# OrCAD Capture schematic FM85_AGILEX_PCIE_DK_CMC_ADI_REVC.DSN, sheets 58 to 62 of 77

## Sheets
58 PWR - 12V to 3.3V: size B
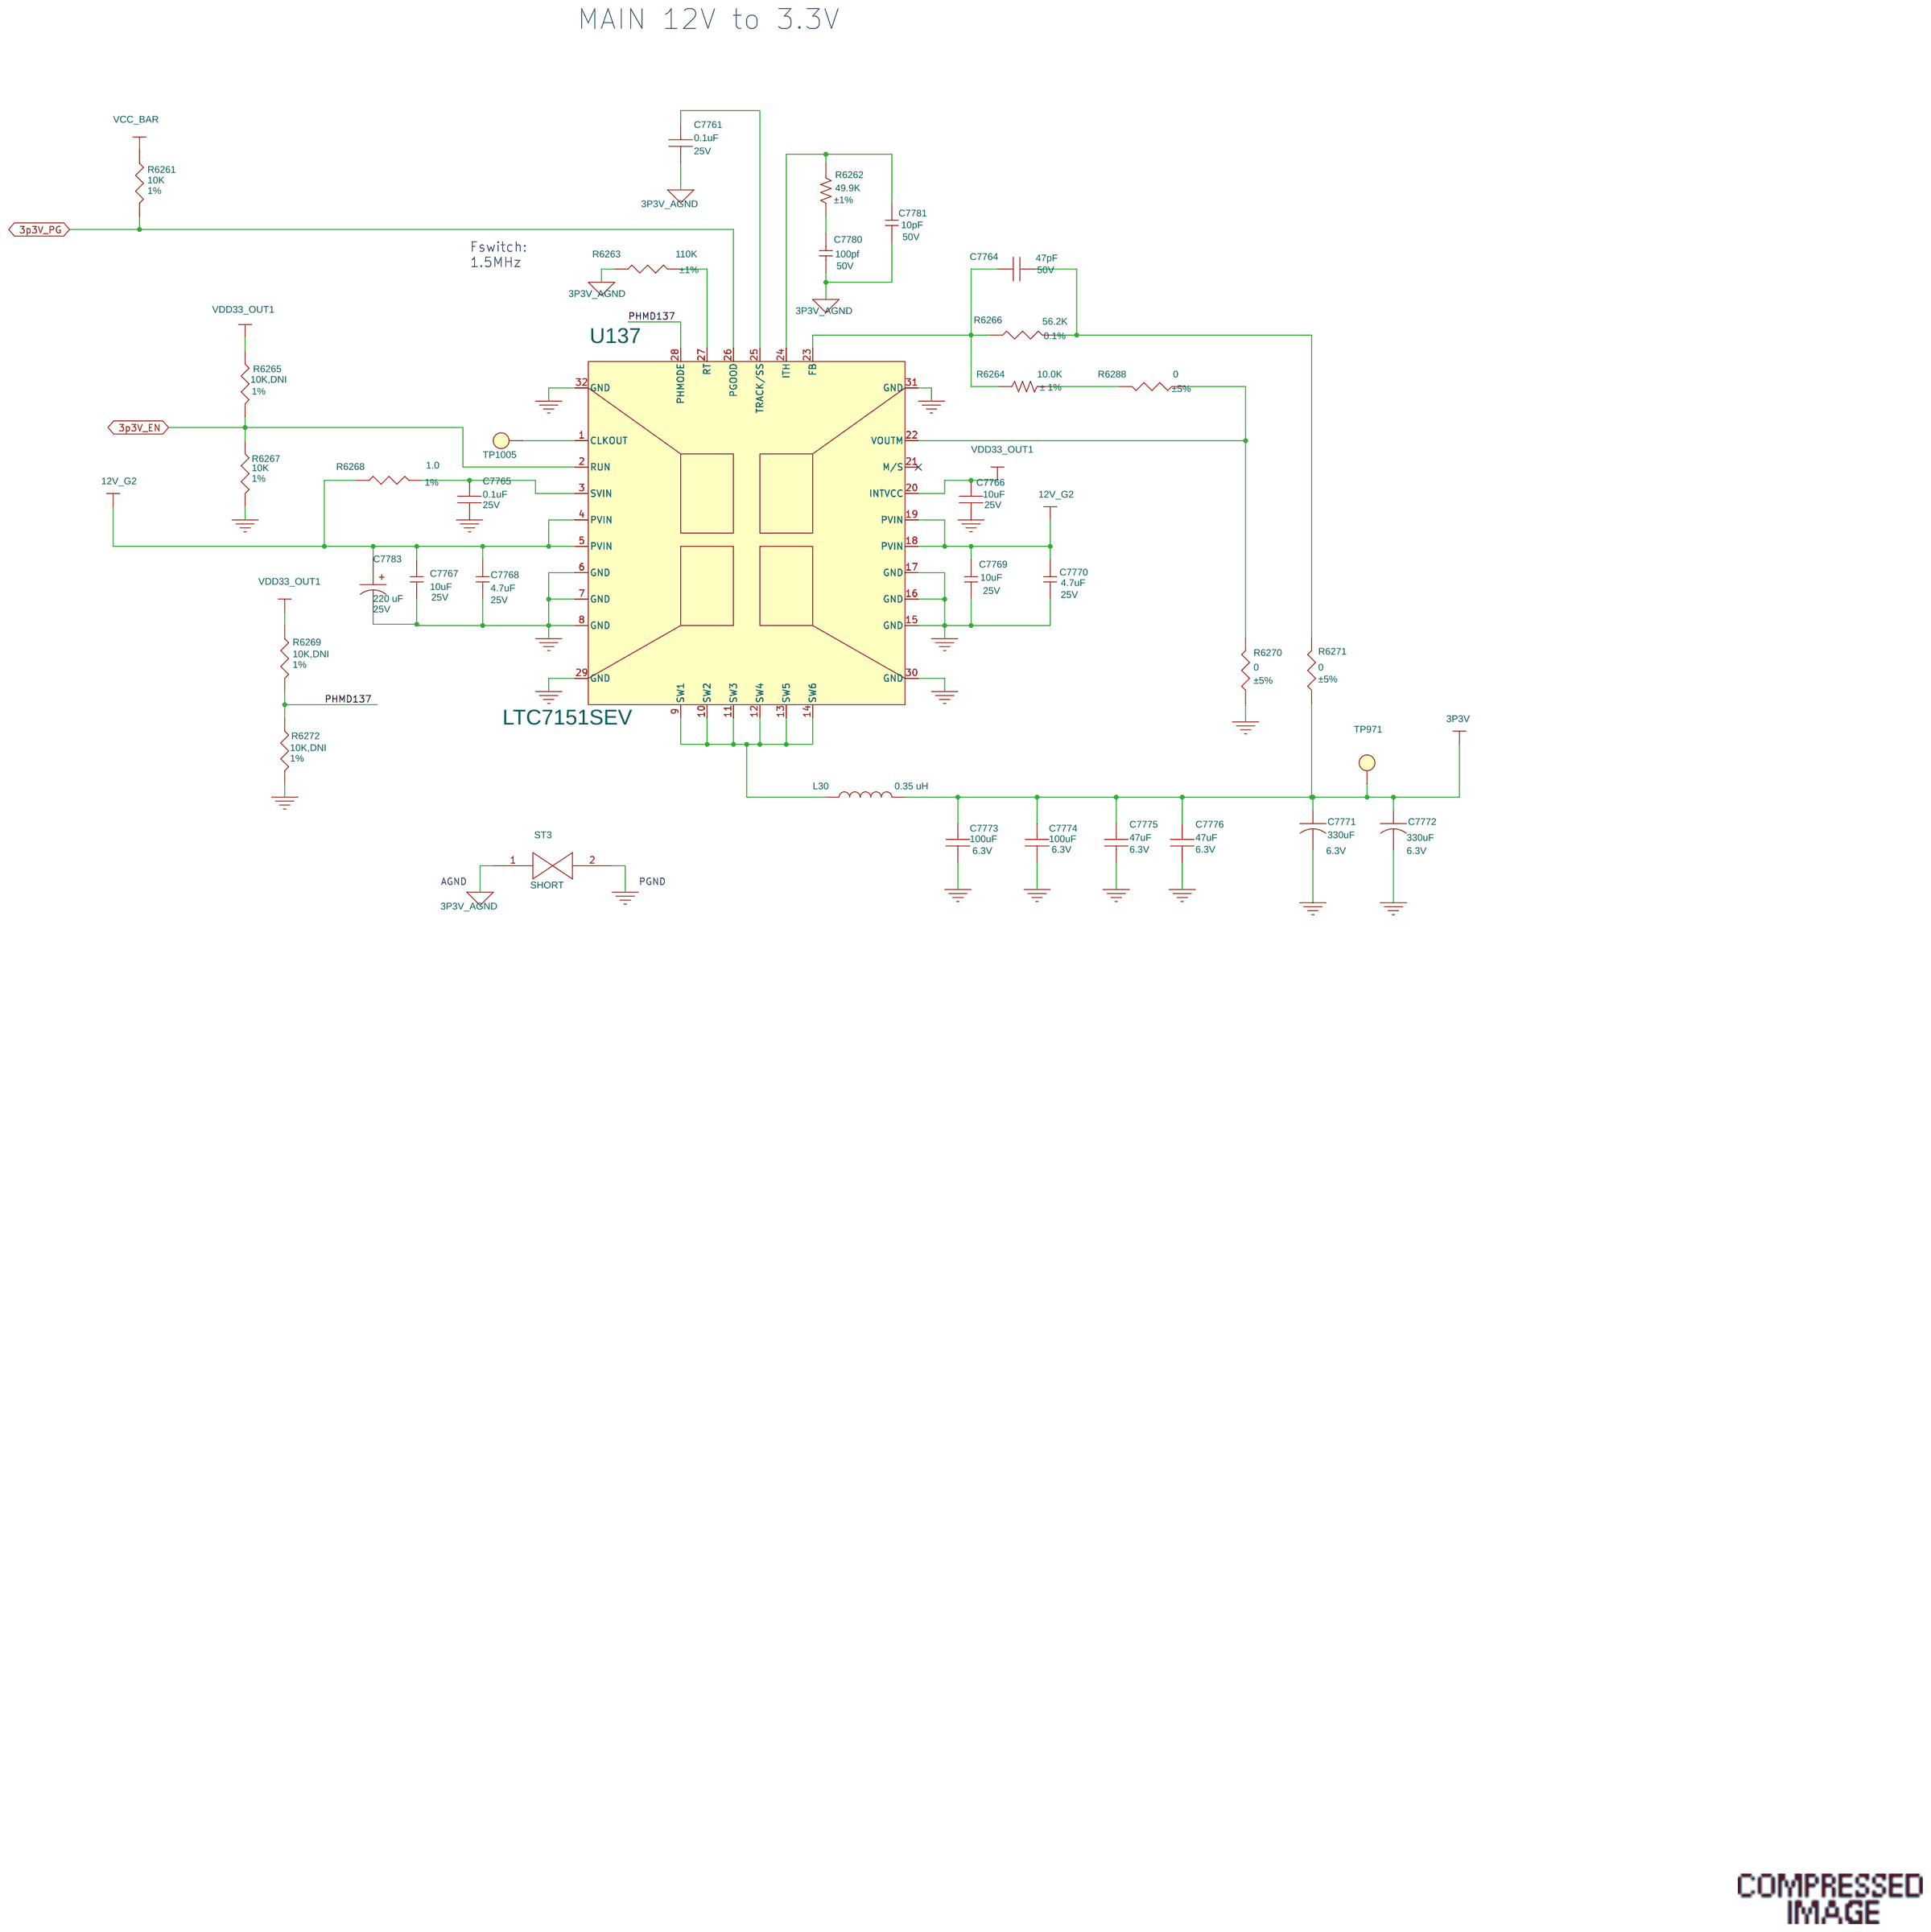
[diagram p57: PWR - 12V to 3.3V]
59 PWR - VCCR_CORE: size C
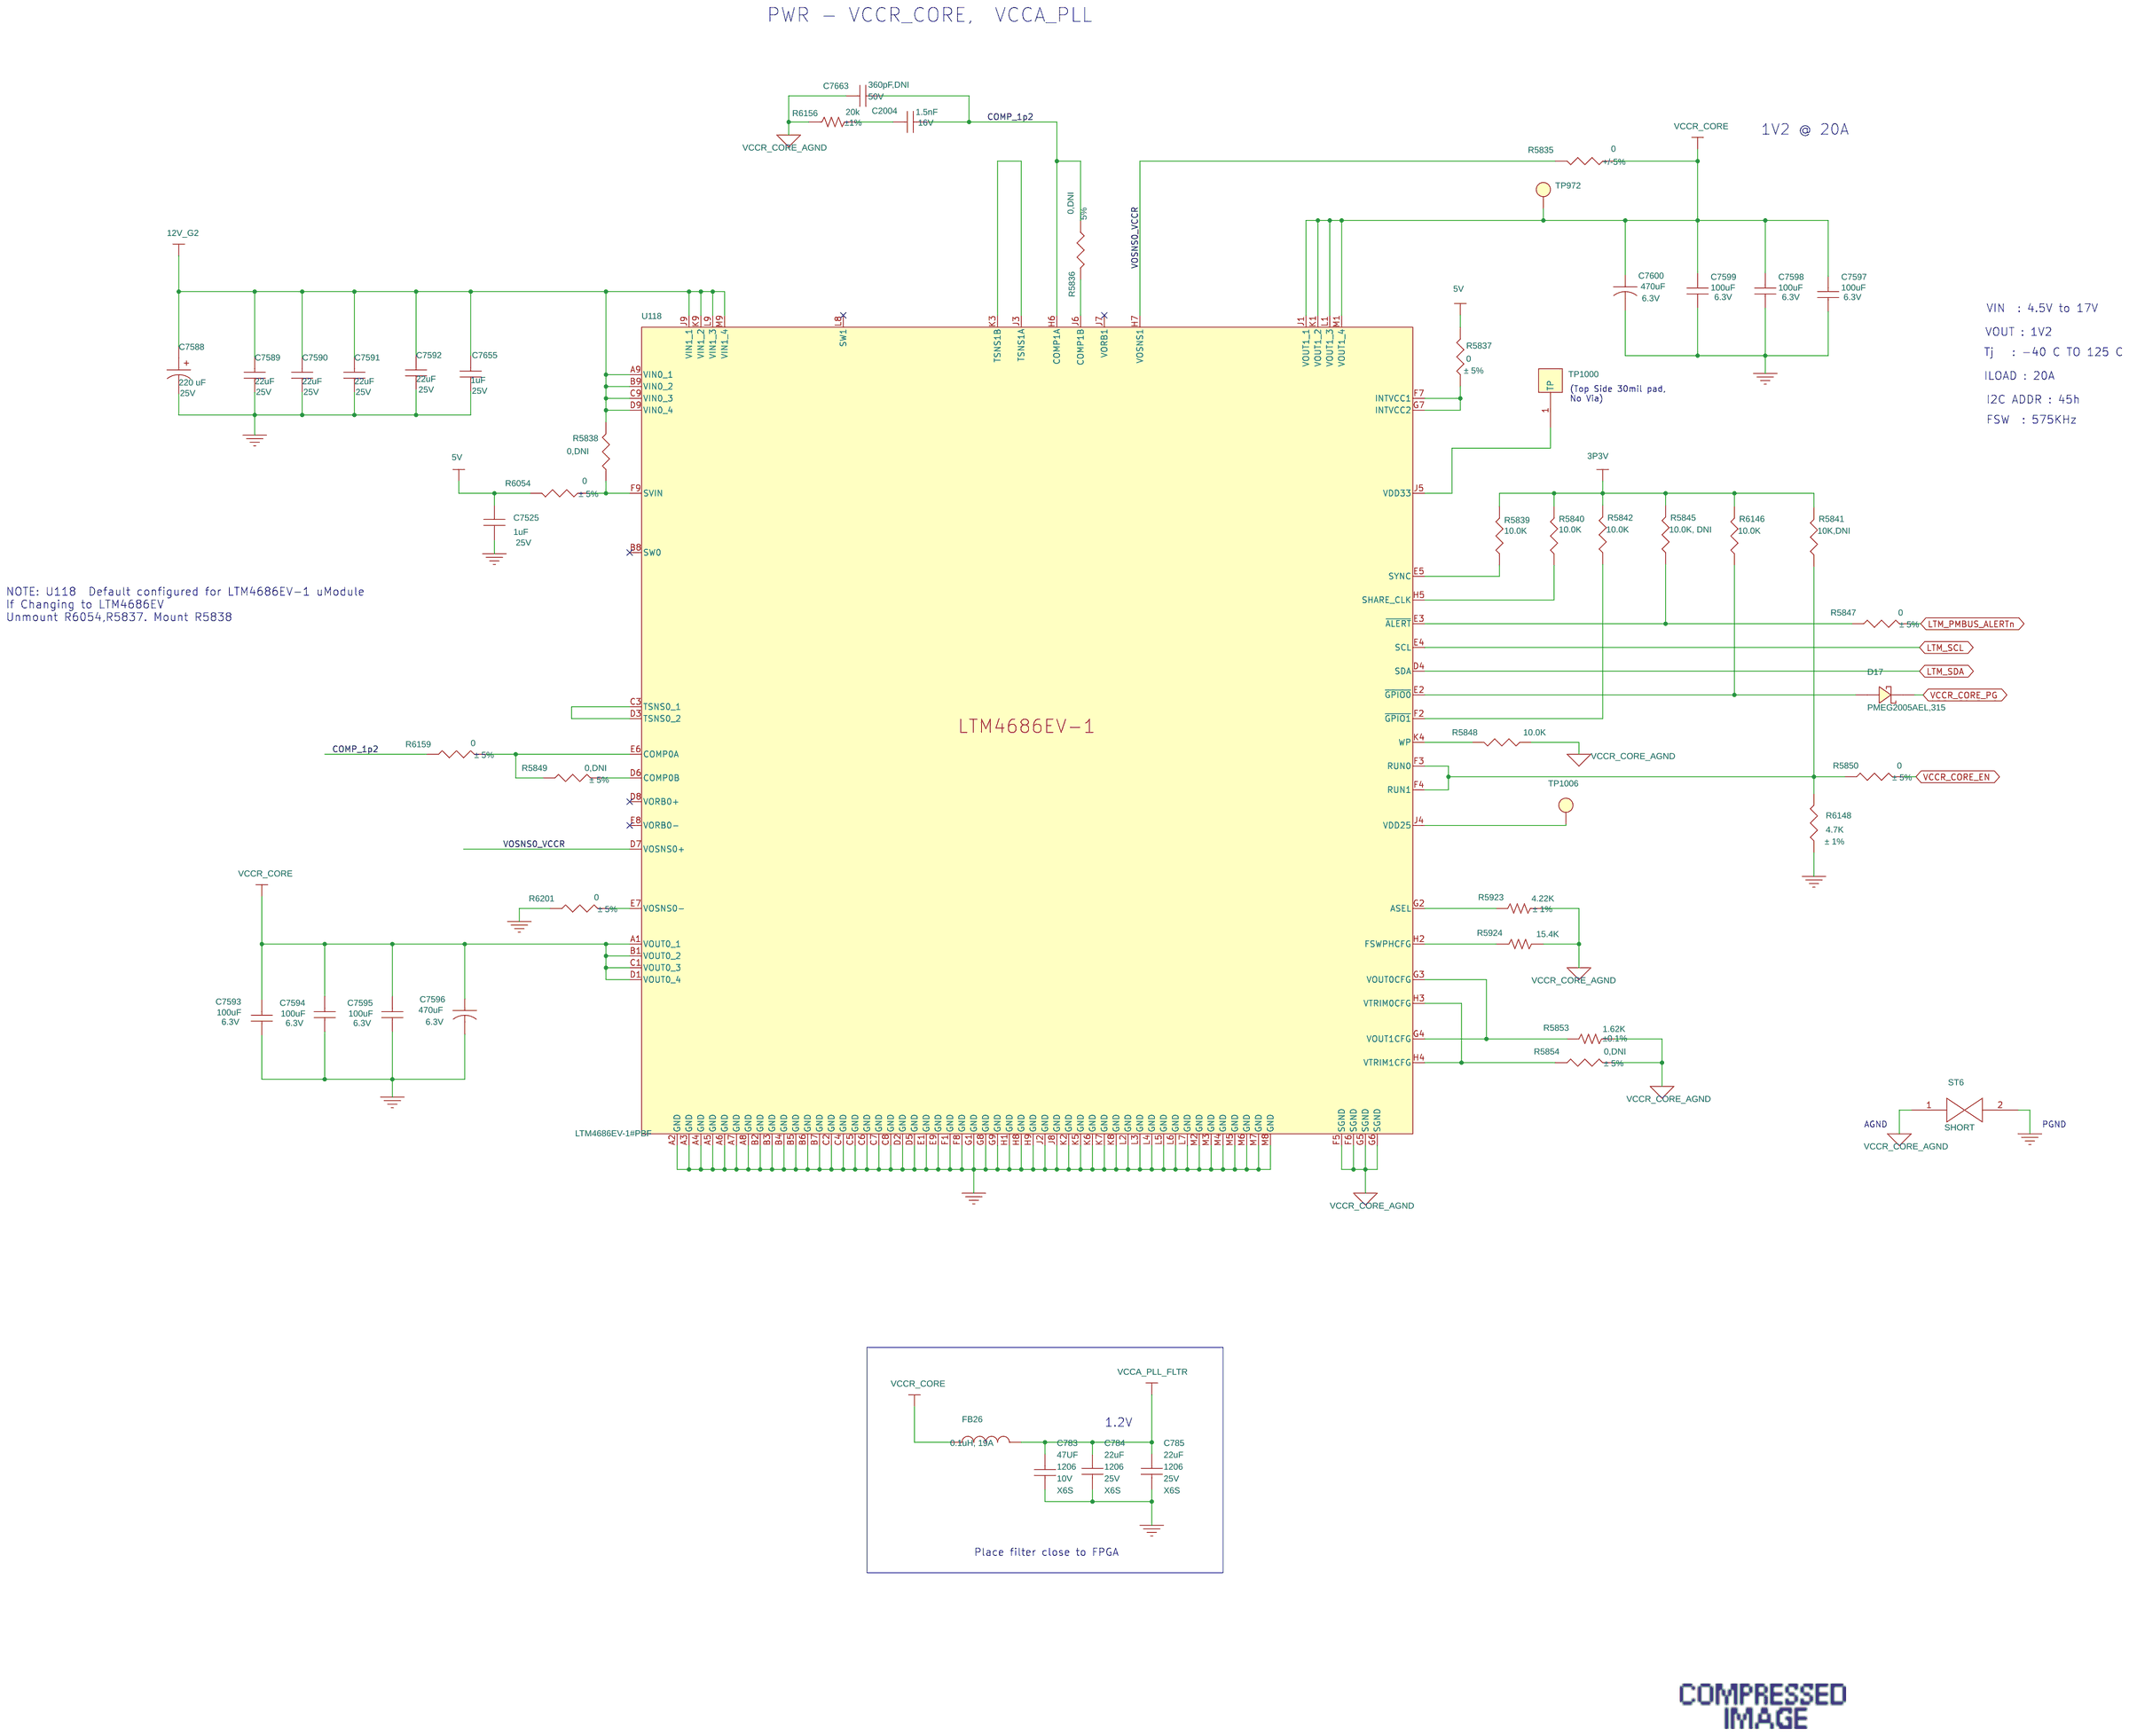
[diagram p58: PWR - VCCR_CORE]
60 PWR -VCCED_GXR: size C
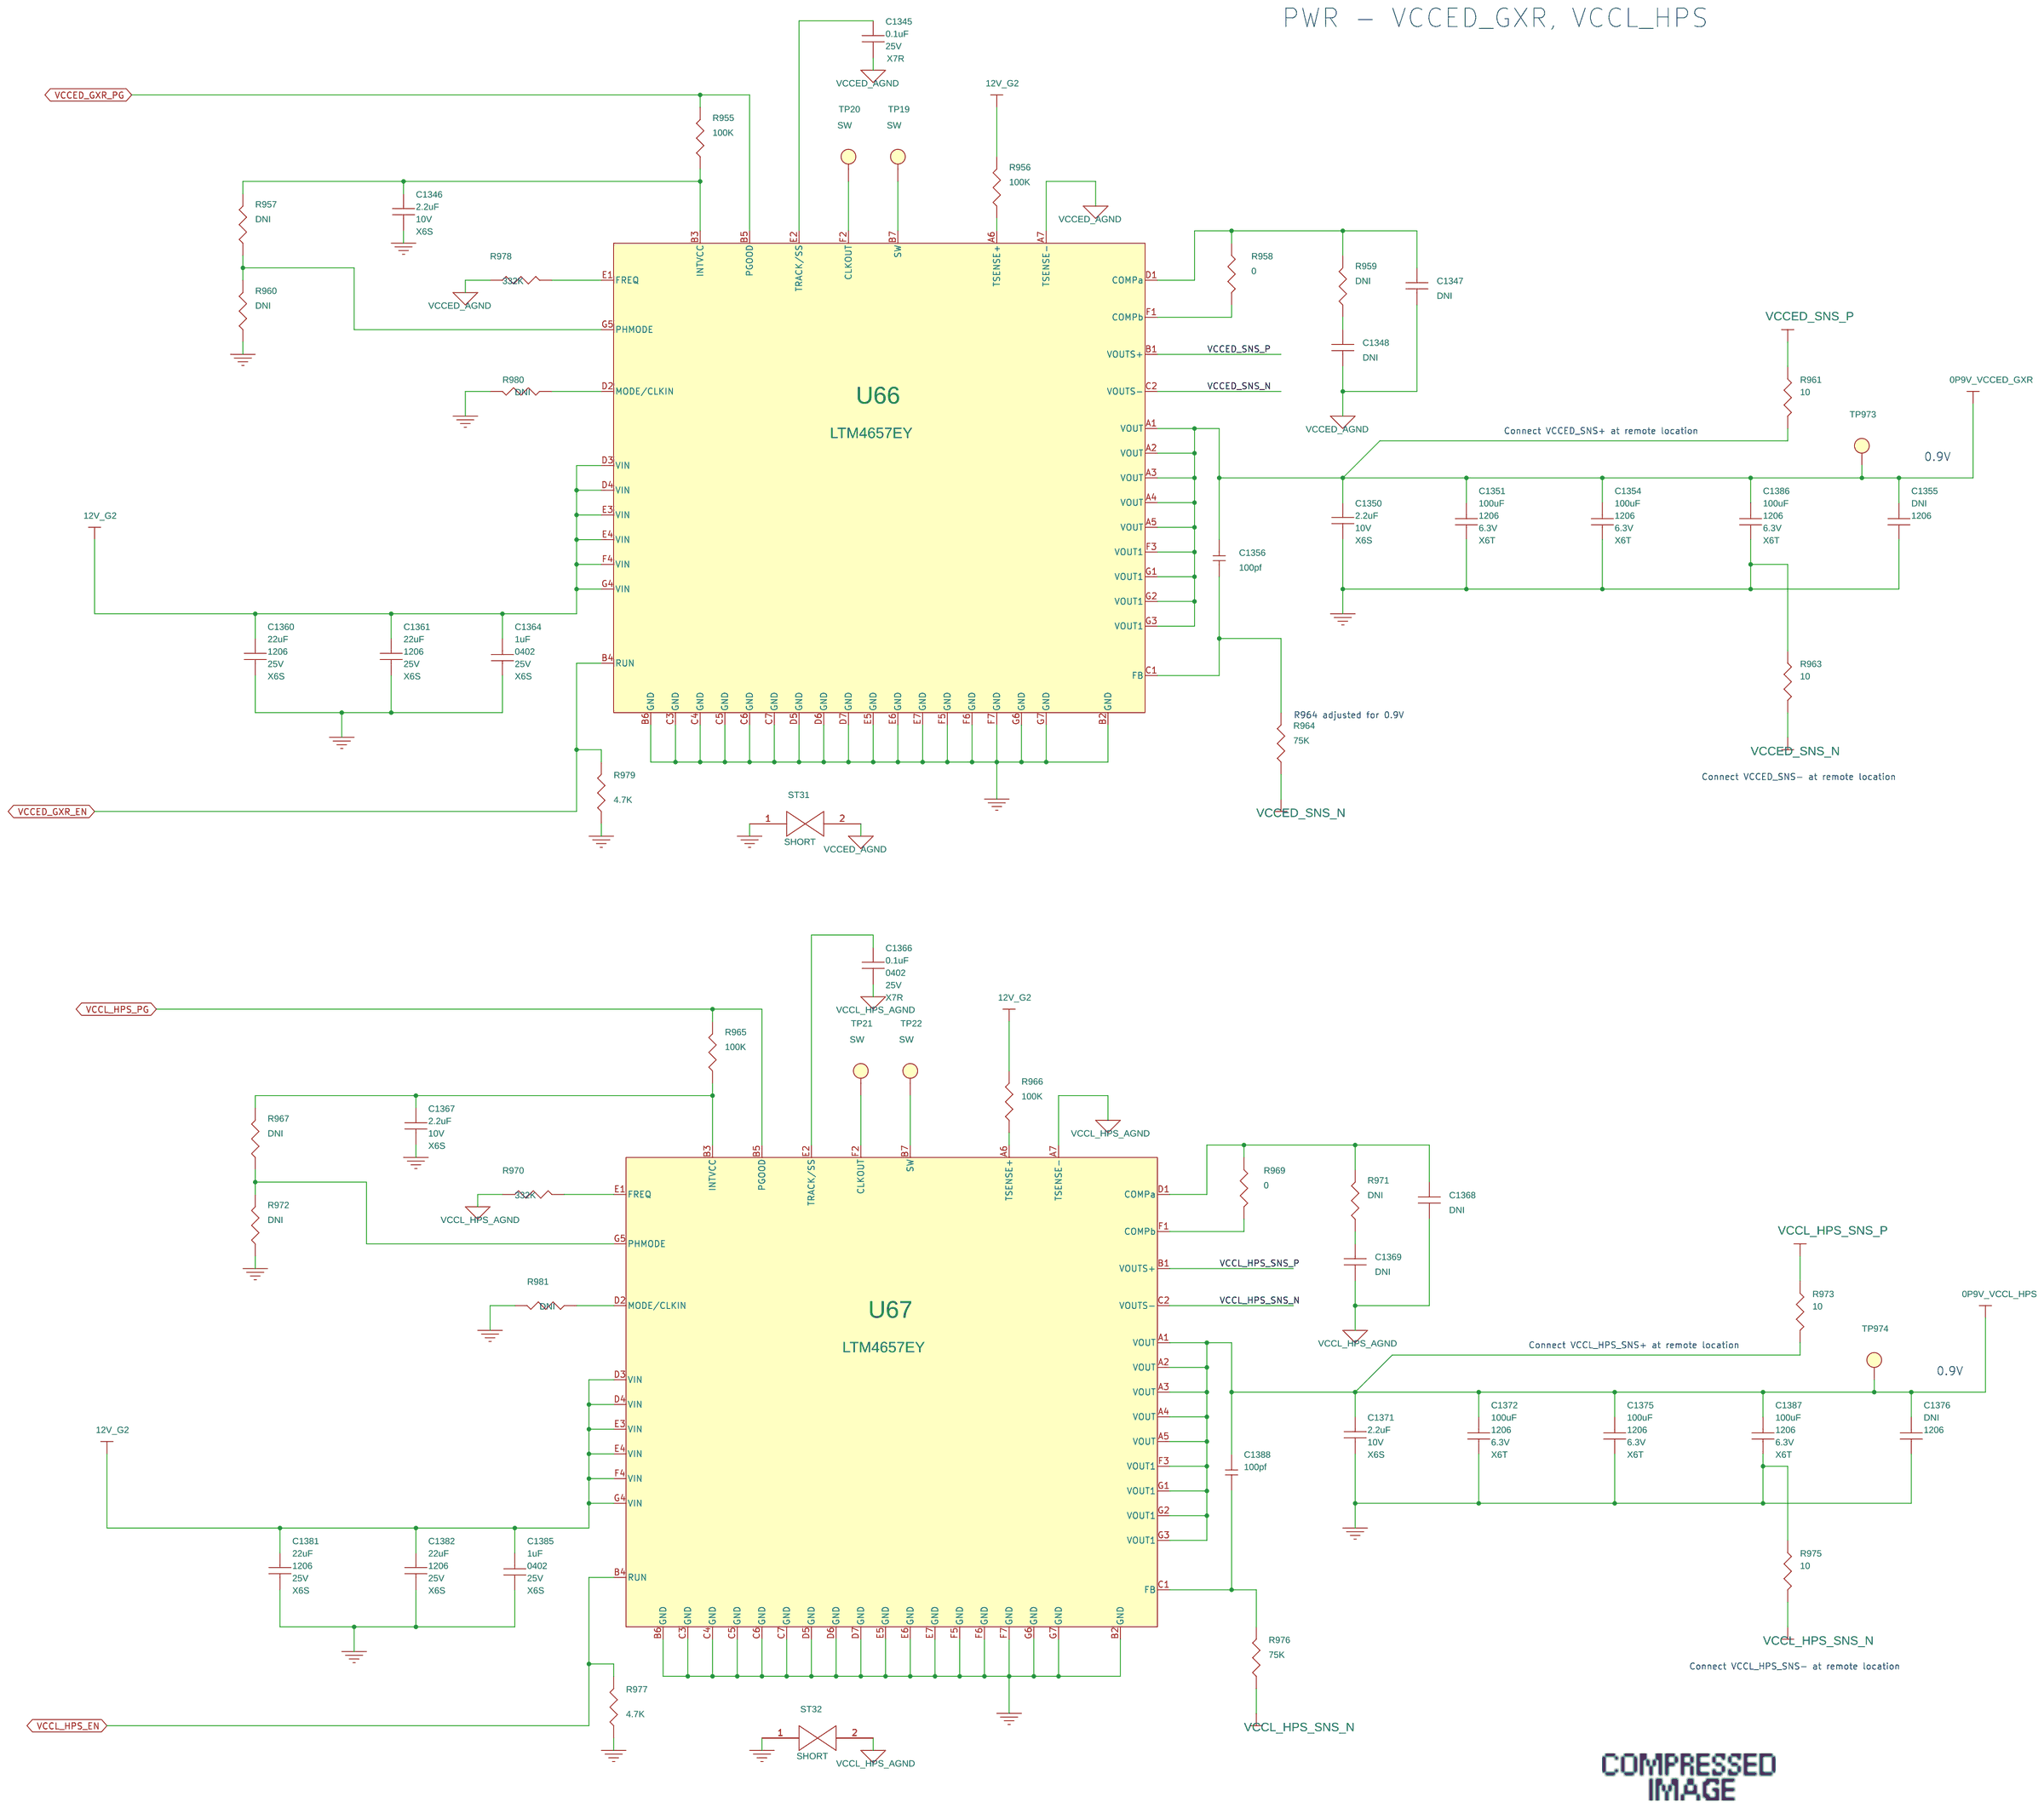
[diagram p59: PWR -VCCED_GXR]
61 PWR - VCCERT_FGT_GXF: size B
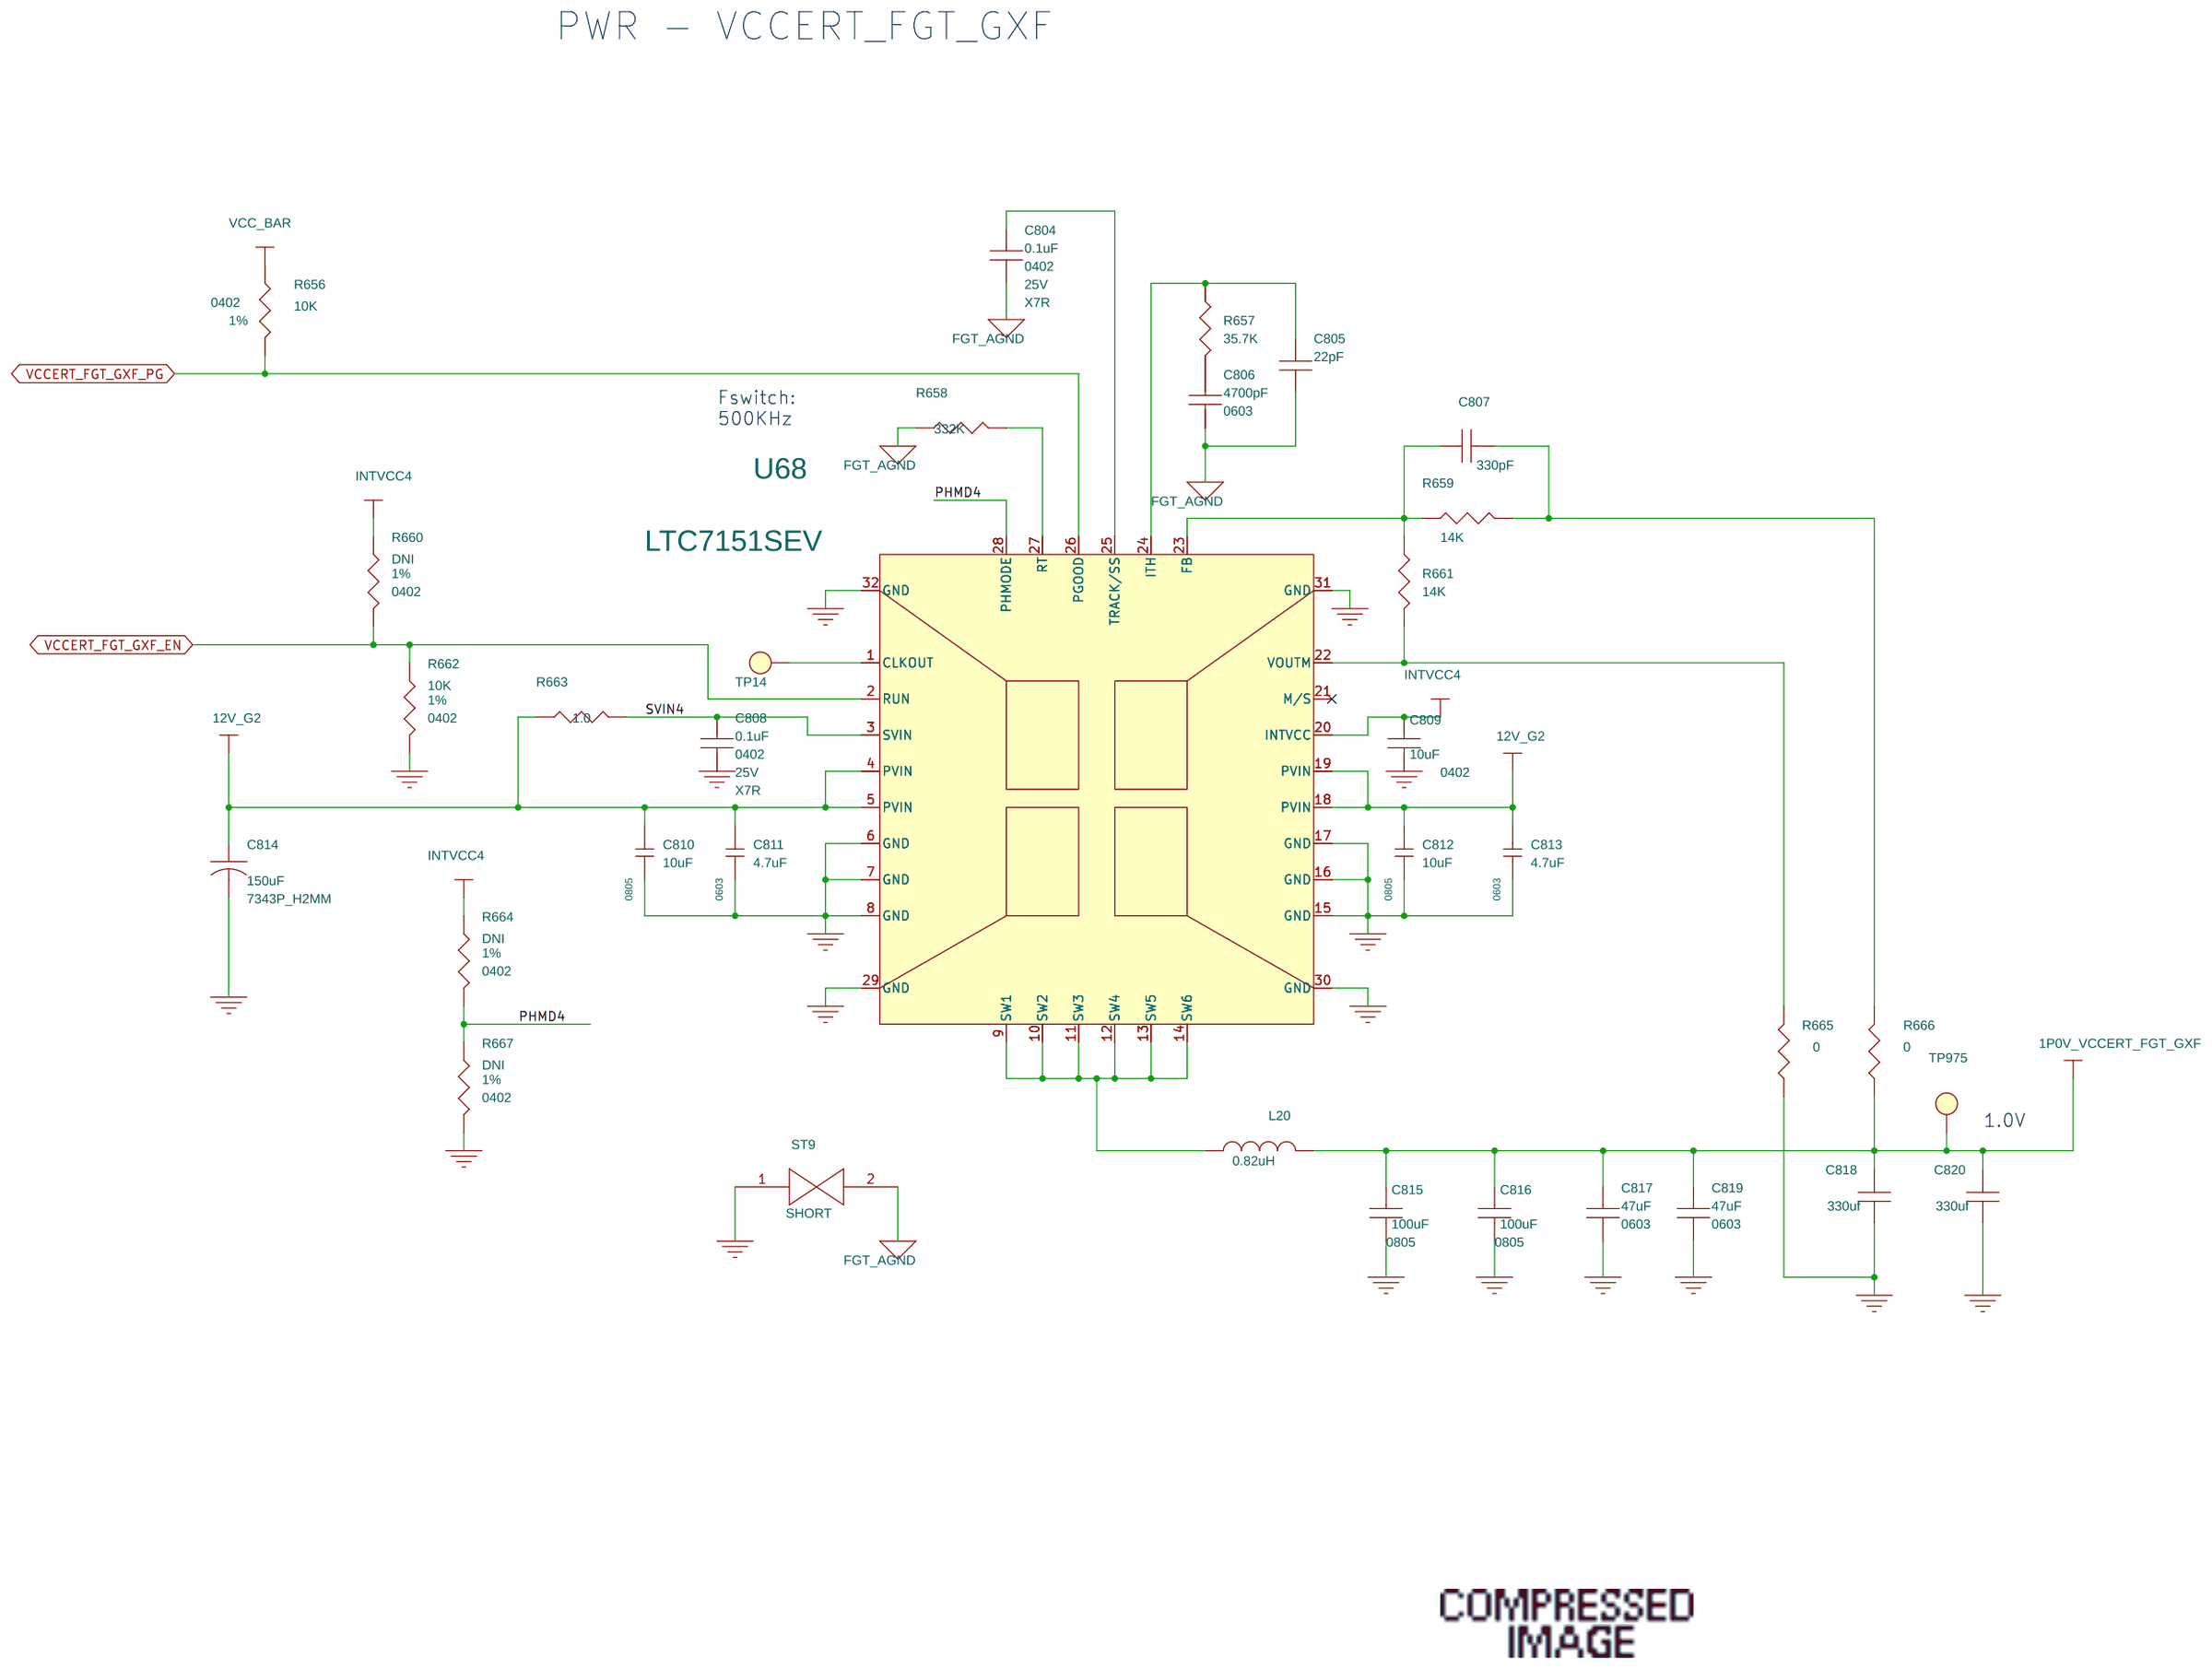
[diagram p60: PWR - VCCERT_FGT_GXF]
62 PWR -VCCRT_GXR: size B
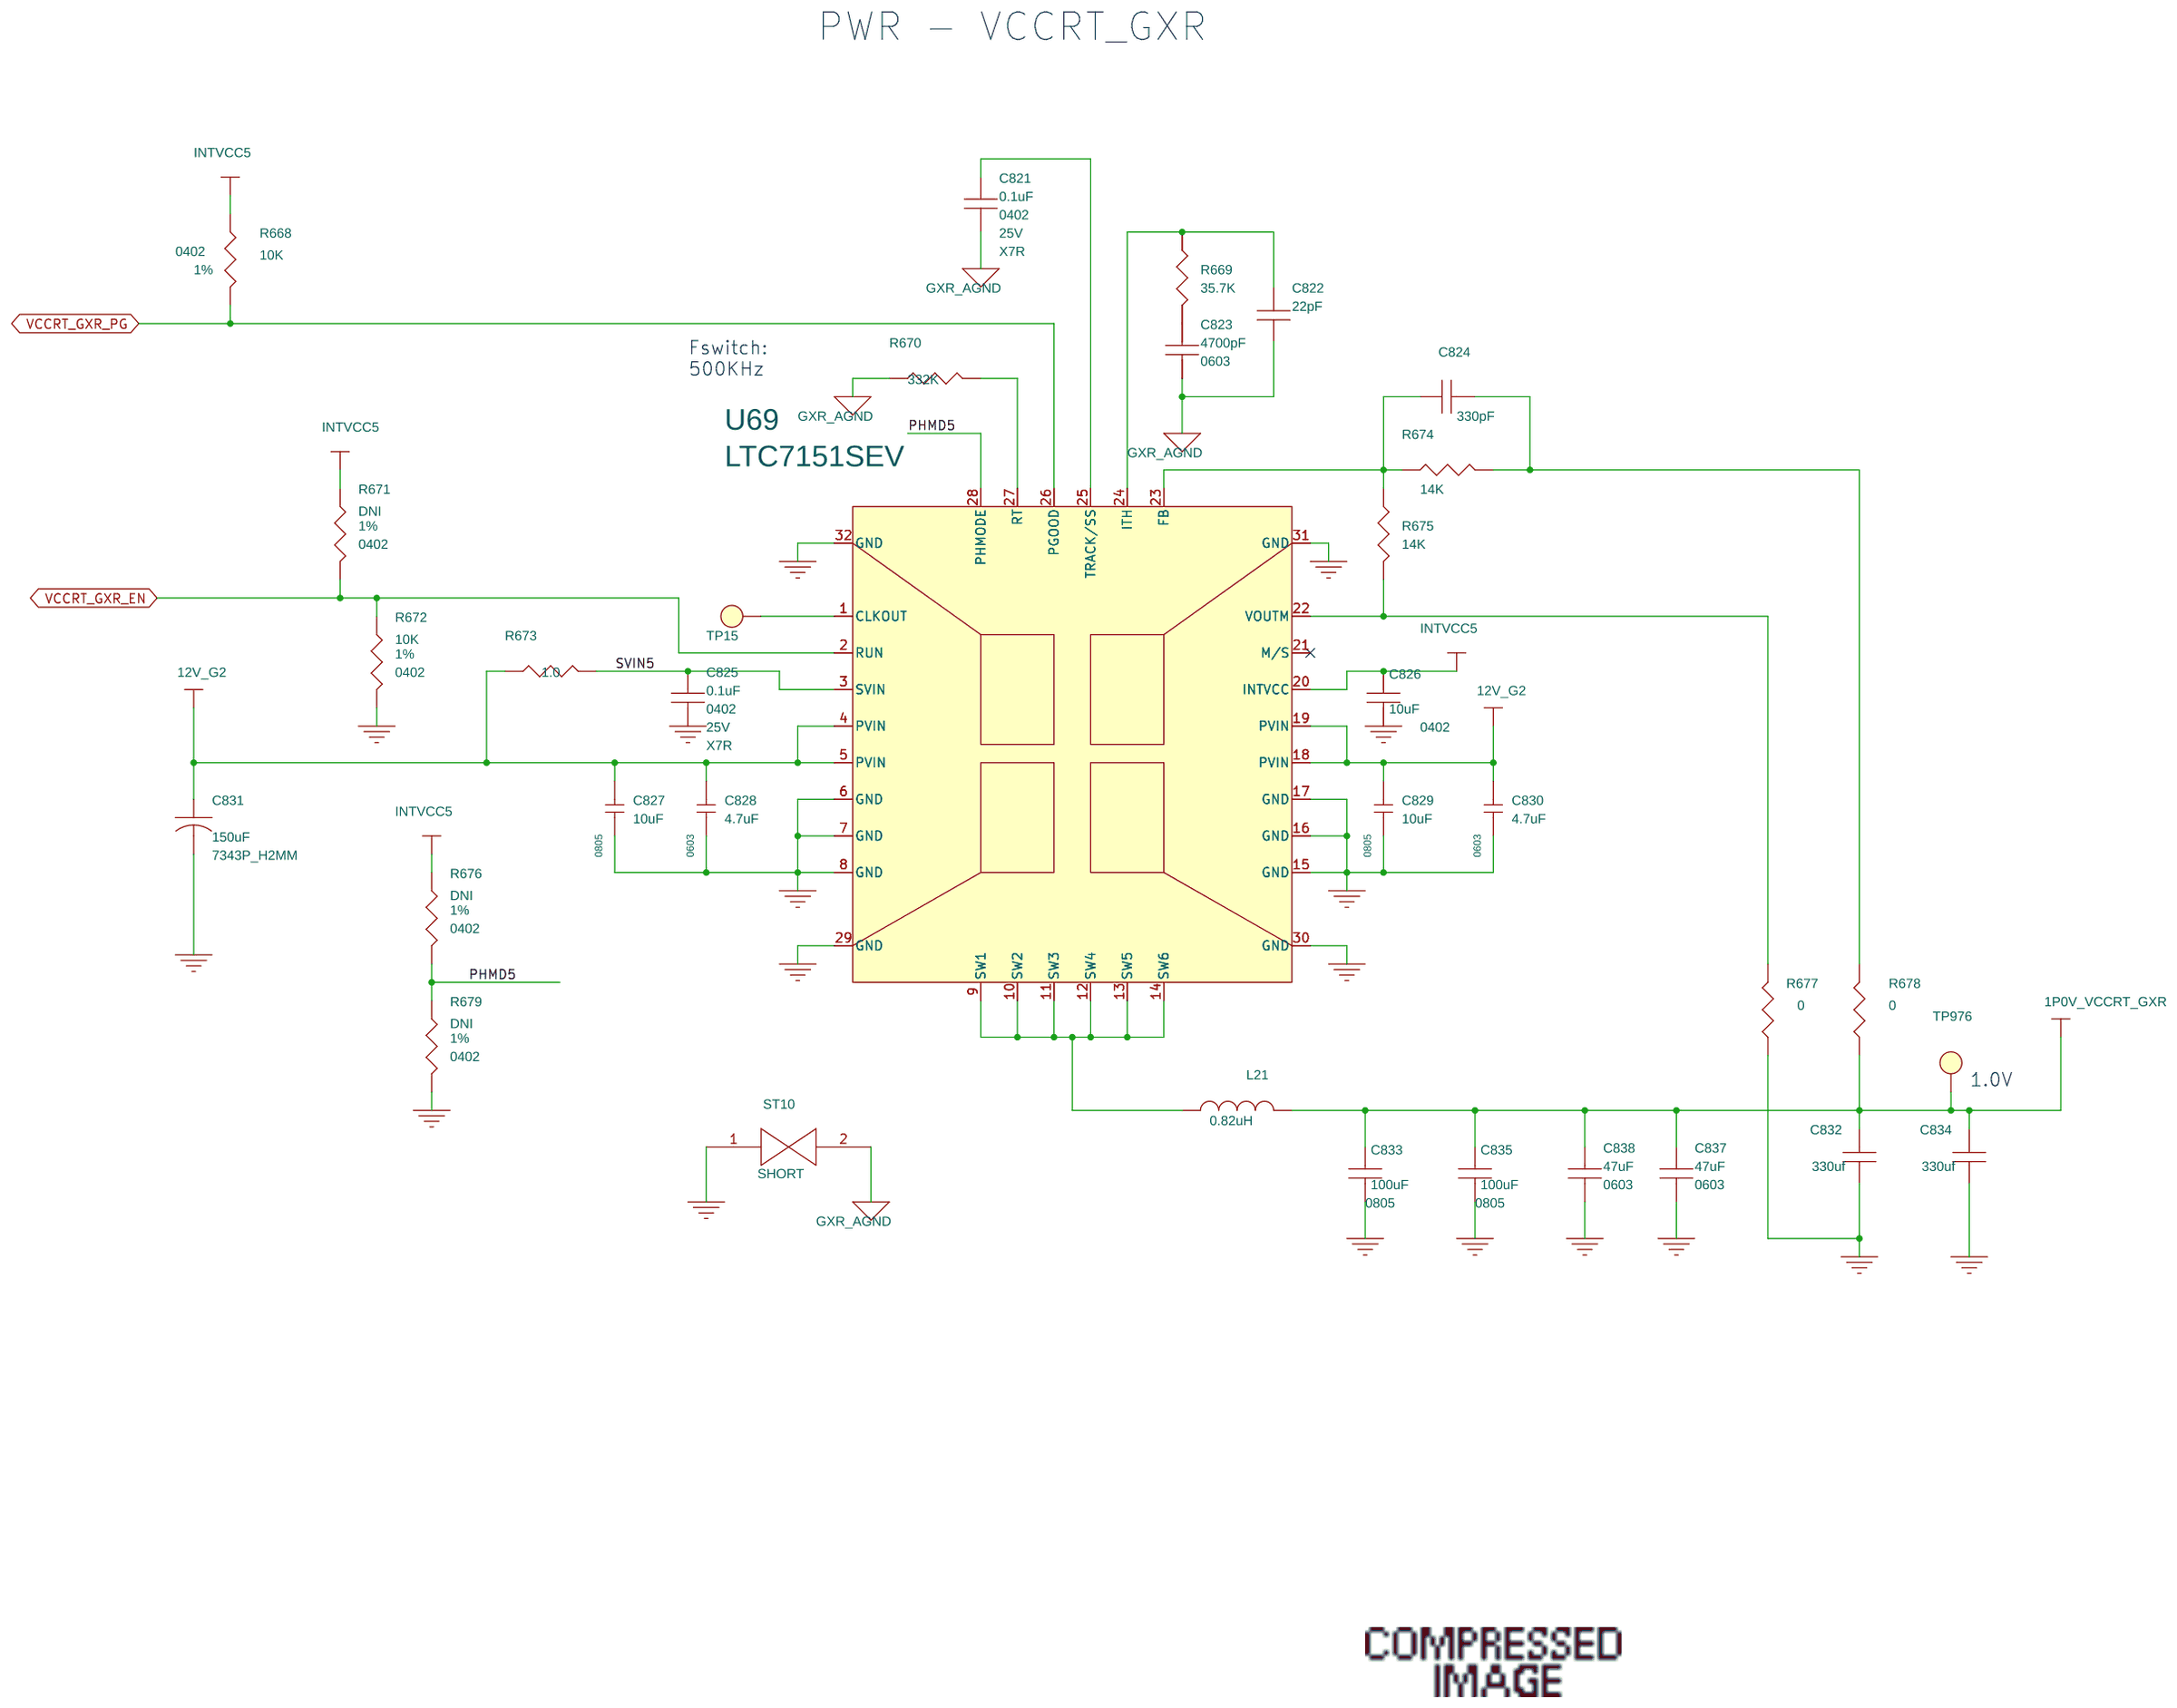
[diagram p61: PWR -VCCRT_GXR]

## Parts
sheet PWR - 12V to 3.3V
C7761  0.1uF  [0402]
C7764  47pF  [0402]
C7765  0.1uF  [0402]
C7766  10uF  [0805]
C7767  10uF  [0805]
C7768  4.7uF  [0603]
C7769  10uF  [0805]
C7770  4.7uF  [0603]
C7771  330uF  [7343P]
C7772  330uF  [7343P]
C7773  100uF  [0805]
C7774  100uF  [0805]
C7775  47uF  [0603]
C7776  47uF  [0603]
C7780  100pf  [0402]
C7781  10pF  [0402]
C7783  220 uF  [CT7361-20]
L30  0.35 uH  [IND_XGL5030]
R6261  10K  [0402]
R6262  49.9K  [0402]
R6263  110K  [0402]
R6264  10.0K  [0402]
R6265  10K,DNI  [0402]
R6266  56.2K  [0402]
R6267  10K  [0402]
R6268  1.0  [0402]
R6269  10K,DNI  [0402]
R6270  0  [0402]
R6271  0  [0402]
R6272  10K,DNI  [0402]
R6288  0  [0402]
ST3  SHORT  [SHORT]
TP971  TESTPOINT  [30MIL_TP]
TP1005  TESTPOINT  [30MIL_TP]
U137  LTC7151SEV  [LQFN_28_5MMX4MM]
sheet PWR - VCCERT_FGT_GXF
C804  0.1uF  [0402]
C805  22pF  [0603]
C806  4700pF  [0603]
C807  330pF  [0402]
C808  0.1uF  [0402]
C809  10uF  [0402]
C810  10uF  [0805]
C811  4.7uF  [0603]
C812  10uF  [0805]
C813  4.7uF  [0603]
C814  150uF  [7343P_H2MM]
C815  100uF  [0805]
C816  100uF  [0805]
C817  47uF  [0603]
C818  330uf  [1210]
C819  47uF  [0603]
C820  330uf  [1210]
L20  0.82uH  [XEL4020-821]
R656  10K  [0402]
R657  35.7K  [0402]
R658  332K  [0402]
R659  14K  [0402]
R660  DNI  [0402]
R661  14K  [0402]
R662  10K  [0402]
R663  1.0  [0402]
R664  DNI  [0402]
R665  0  [0402]
R666  0  [0402]
R667  DNI  [0402]
ST9  SHORT  [SHORT]
TP14  TESTPOINT  [30MIL_TP]
TP975  TESTPOINT  [30MIL_TP]
U68  LTC7151SEV  [LQFN_28_5MMX4MM]
sheet PWR - VCCR_CORE
C783  47UF  [1206]
C784  22uF  [1206]
C785  22uF  [1206]
C2004  1.5nF  [0402]
C7525  1uF  [0402]
C7588  220 uF  [CT7361-20]
C7589  22uF  [1206]
C7590  22uF  [1206]
C7591  22uF  [1206]
C7592  22uF  [1206]
C7593  100uF  [1206]
C7594  100uF  [1206]
C7595  100uF  [1206]
C7596  470uF  [D2E]
C7597  100uF  [1206]
C7598  100uF  [1206]
C7599  100uF  [1206]
C7600  470uF  [D2E]
C7655  1uF  [0402]
C7663  360pF,DNI  [0402]
D17  PMEG2005AEL,315  [DIO_SOD882]
FB26  0.1uH, 19A  [SL1616A-R10MHF]
R5835  0  [0402]
R5836  0,DNI  [0402]
R5837  0  [0402]
R5838  0,DNI  [0402]
R5839  10.0K  [0402]
R5840  10.0K  [0402]
R5841  10K,DNI  [0402]
R5842  10.0K  [0402]
R5845  10.0K, DNI  [0402]
R5847  0  [0402]
R5848  10.0K  [0402]
R5849  0,DNI  [0402]
R5850  0  [0402]
R5853  1.62K  [RESC1005X40L20L]
R5854  0,DNI  [0402]
R5923  4.22K  [0402]
R5924  15.4K  [0402]
R6054  0  [0402]
R6146  10.0K  [0402]
R6148  4.7K  [0402]
R6156  20k  [0402]
R6159  0  [0402]
R6201  0  [0402]
ST6  SHORT  [SHORT]
TP972  TESTPOINT  [30MIL_TP]
TP1000  TESTPOINT  [30mil_TP]
TP1006  TESTPOINT  [30MIL_TP]
U118  LTM4686EV-1#PBF  [LGA108C127P9X12_1190X1600X192N]
sheet PWR -VCCED_GXR
C1345  0.1uF  [0402]
C1346  2.2uF  [0402]
C1347  DNI  [0402]
C1348  DNI  [0402]
C1350  2.2uF  [0402]
C1351  100uF  [1206]
C1354  100uF  [1206]
C1355  DNI  [1206]
C1356  100pf  [0402]
C1360  22uF  [1206]
C1361  22uF  [1206]
C1364  1uF  [0402]
C1366  0.1uF  [0402]
C1367  2.2uF  [0402]
C1368  DNI  [0402]
C1369  DNI  [0402]
C1371  2.2uF  [0402]
C1372  100uF  [1206]
C1375  100uF  [1206]
C1376  DNI  [1206]
C1381  22uF  [1206]
C1382  22uF  [1206]
C1385  1uF  [0402]
C1386  100uF  [1206]
C1387  100uF  [1206]
C1388  100pf  [0402]
R955  100K  [0402]
R956  100K  [0402]
R957  DNI  [0402]
R958  0  [0402]
R959  DNI  [0402]
R960  DNI  [0402]
R961  10  [0402]
R963  10  [0402]
R964  75K  [0402]
R965  100K  [0402]
R966  100K  [0402]
R967  DNI  [0402]
R969  0  [0402]
R970  332K  [0402]
R971  DNI  [0402]
R972  DNI  [0402]
R973  10  [0402]
R975  10  [0402]
R976  75K  [0402]
R977  4.7K  [0402]
R978  332K  [0402]
R979  4.7K  [0402]
R980  DNI  [0402]
R981  DNI  [0402]
ST31  SHORT  [SHORT]
ST32  SHORT  [SHORT]
TP19  TEST PAD  [PADSTYLE1]
TP20  TEST PAD  [PADSTYLE1]
TP21  TEST PAD  [PADSTYLE1]
TP22  TEST PAD  [PADSTYLE1]
TP973  TESTPOINT  [30MIL_TP]
TP974  TESTPOINT  [30MIL_TP]
U66  LTM4657EY  [LTC-BGA-49-1518]
U67  LTM4657EY  [LTC-BGA-49-1518]
sheet PWR -VCCRT_GXR
C821  0.1uF  [0402]
C822  22pF  [0603]
C823  4700pF  [0603]
C824  330pF  [0402]
C825  0.1uF  [0402]
C826  10uF  [0402]
C827  10uF  [0805]
C828  4.7uF  [0603]
C829  10uF  [0805]
C830  4.7uF  [0603]
C831  150uF  [7343P_H2MM]
C832  330uf  [1210]
C833  100uF  [0805]
C834  330uf  [1210]
C835  100uF  [0805]
C837  47uF  [0603]
C838  47uF  [0603]
L21  0.82uH  [XEL4020-821]
R668  10K  [0402]
R669  35.7K  [0402]
R670  332K  [0402]
R671  DNI  [0402]
R672  10K  [0402]
R673  1.0  [0402]
R674  14K  [0402]
R675  14K  [0402]
R676  DNI  [0402]
R677  0  [0402]
R678  0  [0402]
R679  DNI  [0402]
ST10  SHORT  [SHORT]
TP15  TESTPOINT  [30MIL_TP]
TP976  TESTPOINT  [30MIL_TP]
U69  LTC7151SEV  [LQFN_28_5MMX4MM]

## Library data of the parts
C804 C808 C821 C825 C7761 C7765 = CAP: CAP CER 0.1UF 25V 20% X7R 0402; Dielectric: X7R; Item Num: A36096-112; LIFECYCLE_PHASE: Active; Lead Free Status: Lead Free; Manufacturer: Murata; Manufacturer Part Num: GRM155R71E104KE14D; Num Pins: 2; Part Class: CAPACITORS; RATED_VOLTAGE: 25V; RoHS Compliant: RoHS Compliant; Tolerance: 10%
C7764 = CAP: CAP,0402,47PF,50V,DC,5%; Item Num: A78596-001; Manufacturer: Panasonic; Manufacturer Part Num: ECJ-0EC1H470J; RATED_VOLTAGE: 50V
C7766 = CAP: CAP - CERAMIC, SMD/SMT 0805 25VDC 10uF 10% X5R; Item Num: H48130-001; Lead Free Status: Lead Free; Manufacturer: Taiyo Yuden; Manufacturer Part Num: TMK212BBJ106KGHT; Num Pins: 2; PART_SUBCLASS: CAPACITORS; Part Class: CAPACITORS; Part Number: TMK212BBJ106KGHT; RATED_VOLTAGE: 25V; RoHS Compliant: RoHS Compliant; TOLERANCE: ±10%; Temperature Coefficient: X5R; Voltage: 25V
C7767 C7769 = Cap,_NP,_1206: CAP - CERAMIC, SMD/SMT 0805 25VDC 10uF 10% X5R; Dielectric: X5R; Item Num: H48130-001; Manufacturer: Taiyo Yuden; Manufacturer Part Num: TMK212BBJ106KGHT; Part Number: TMK212BBJ106KGHT; RATED_VOLTAGE: 25V; TOLERANCE: ±10%; Voltage: 25V
C7768 C7770 = Cap,_NP,_1206: CAP CER 4.7UF 25V ±10% X5R 0603; Agile Part Number: P03-15063R; Dielectric: X5R; Item Num: K13740-001; Manufacturer: Murata; Manufacturer Part Num: GRM188R61E475KE11D; Part Number: GRM188R61E475KE11D; RATED_VOLTAGE: 25V; TOLERANCE: ±10%; Voltage: 25V
C7771 C7772 = PCAP: CAP OXI LOESR 330UF 6.3V,20%SMD; Item Num: E85955-001; LIFECYCLE_PHASE: Active; Lead Free Status: Lead Free; MFR_LIFECYCLE: Active; Manufacturer: AVX LTD; Manufacturer Part Num: NOSE337M006R0080; Num Pins: 2; PART_SUBCLASS: CAPACITORS; RATED_VOLTAGE: 6.3V; RoHS Compliant: RoHS Compliant; TOLERANCE: +/-20%
C815 C816 C833 C835 C7773 C7774 = CAP: CAP CER 100UF 6.3V X5R 0805; Item Num: K32109-001; Lead Free Status: Lead Free; Manufacturer: Murata Electronics North America; Manufacturer Part Num: GRM21BR60J107ME15L; Num Pins: 2; PART_SUBCLASS: CAPACITORS; Part Class: CAPACITORS; RATED_VOLTAGE: 6.3V; RoHS Compliant: RoHS Compliant; Temperature Coefficient: X5R
C817 C819 C837 C838 C7775 C7776 = CAP: CAP CER 47UF 6.3V X5R 0603; Item Num: K31624-001; MFR_LIFECYCLE: Active; Manufacturer: Murata Electronics North America; Manufacturer Part Num: GRM188R60J476ME15D; Num Pins: 2; PART_SUBCLASS: CAPACITORS; RATED_VOLTAGE: 6.3V; RoHS Compliant: RoHS Compliant; TOLERANCE: 20%
C7780 = Cap,_NP,_0402: CAP, CERAMIC, 100pF, 0402, 5%, 50VDC, NPO; Item Num: K13768-001; Manufacturer: Murata; Manufacturer Part Num: GRM1555C1H101JA01D; RATED_VOLTAGE: 50V
C7781 = Cap,_NP,_0402: CAP,0402,10PF,50V,5%; Item Num: C17122-001; Manufacturer: KEMET; Manufacturer Part Num: C0402C100J5GACTU; RATED_VOLTAGE: 50V
C7783 = TCN4227M025R0100: Item Num: M75353-001; RATED_VOLTAGE: 25V
L30 = XGL5030-351MEC: IND,0.35UH,24.5A,2.2MOHM; Item Num: M85044-001
R656 R662 R668 R672 R6261 R6267 = RESISTOR: RES,10.0K OHMS,1.0%,1/16W, 0402; AGILE_LINK: http://sj-agile9app/Agile/PLMServlet?action=OpenEmailObject&classid=10000&objid=146548997; Item Num: A93548-034; LIFECYCLE_PHASE: Active; Lead Free Status: No; MFR_LIFECYCLE: Active; Manufacturer: Panasonic; Manufacturer Part Num: ERJ-2RKF1002X; Num Pins: 2; PART_SUBCLASS: RESISTORS; POWER: 1/16W; RoHS Compliant: Yes; TOLERANCE: 1%
R6262 = Resistor,_0402: RES 49.9K ohm, 1/16W 1% 0402 SMD; Agile Part Number: P02-15647R; Item Num: E81533-001; Manufacturer: PANASONIC INDUSTRIAL; Manufacturer Part Num: ERJ-2RKF4992X; Power: 1/16W; TOLERANCE: ±1%
R6263 = RESISTOR: RESD,0402,1%,1/16W,110K; Item Num: E30631-001; Lead Free Status: No; Manufacturer: CYNTEC CO.LTD; Manufacturer Part Num: RR0510S-114-FN; Num Pins: 2; Part Class: RESISTORS; Price: 0; RoHS Compliant: Yes; Tolerance: ±1%
R6264 = Resistor,_0402: RES,10.0K OHMS,1.0%,1/16W, 0402; Agile Part Number: P02-17688R; Item Num: K28115-001; Manufacturer: Panasonic; Manufacturer Part Num: ERJ-2RKF1002X; Part Number: ERJ-2RKF1002X; Power: 1/16W; TOLERANCE: ± 1%
R660 R664 R667 R671 R676 R679 R6265 R6269 R6272 = RESISTOR: RES,10.0K OHMS,1.0%,1/16W, 0402; AGILE_LINK: http://sj-agile9app/Agile/PLMServlet?action=OpenEmailObject&classid=10000&objid=146548997; Item Num: A93548-034; LIFECYCLE_PHASE: Active; Lead Free Status: No; MFR_LIFECYCLE: Active; Manufacturer: Panasonic; Manufacturer Part Num: ERJ-2RKF1002X; Num Pins: 2; PART_SUBCLASS: RESISTORS; POWER: 1/16W; RESISTANCE: 10K; RoHS Compliant: Yes; TOLERANCE: 1%
R6266 = RESISTOR: RES,SMD,0402,56.2KOHM,0.1%,1/16W; AGILE_LINK: http://sj-agile9app/Agile/PLMServlet?action=OpenEmailObject&classid=10000&objid=146548997; Item Num: J98646-001; LIFECYCLE_PHASE: Active; Lead Free Status: No; MFR_LIFECYCLE: Active; Manufacturer: YAGEO CORP.; Manufacturer Part Num: RT0402BRD0756K2L; Num Pins: 2; PART_SUBCLASS: RESISTORS; POWER: 1/16W; Part Number: RT0402BRD0756K2L; RoHS Compliant: Yes; TOLERANCE: 0.1%
R663 R673 R6268 = RESISTOR: RES,1.0 OHMS,1.0%,1/16W, 0402; AGILE_LINK: http://sj-agile9app/Agile/PLMServlet?action=OpenEmailObject&classid=10000&objid=146548997; Item Num: A93548-210; LIFECYCLE_PHASE: Active; Lead Free Status: No; MFR_LIFECYCLE: Active; Manufacturer: Yageo; Manufacturer Part Num: RC0402FR-071RL; Num Pins: 2; PART_SUBCLASS: RESISTORS; POWER: 1/16W; RoHS Compliant: Yes; TOLERANCE: 1%
R6270 R6271 R6288 = RESISTOR: RES D,0402,0.00 OHM,5.00%,1/16W; Altera Part No.: P02-14020R; Item Num: A93549-001; LIFECYCLE_PHASE: Active; Lead Free Status: No; MFR_LIFECYCLE: Active; Manufacturer: Panasonic; Manufacturer Part Num: ERJ-2GE0R00X; Num Pins: 2; PART_SUBCLASS: RESISTORS; POWER: 1/16W; Part Class: RESISTORS; RoHS Compliant: RoHS Compliant; Tolerance: ±5%
ST3 ST6 ST9 ST10 ST31 ST32 = SHORT
TP14 TP15 TP971-TP976 TP1005 TP1006 = TP,_0.016_,_Thru_Hole
U68 U69 U137 = LTC3543EDCB_0: REGULATOR,20VIN 15A SILENT SW2,15A STEP-DOWN DC/DC; Item Num: M21811-001; Manufacturer: Analog Devices; Manufacturer Part Num: LTC7151SEV#PBF
C805 C822 = CAP_NP: CAPC,C0G,0603,22.000PF,50.000V,+/- 5%,; Item Num: M23241-001; Manufacturer: Murata; Manufacturer Part Num: GRM1885C1H220JA01J
C806 C823 = CAP: CAP CER 4700PF 25V X7R 0603; CAPACITANCE: 0.1uF; Dielectric: X7R; Item Num: M22896-001; LIFECYCLE_PHASE: Active; Lead Free Status: Lead Free; Manufacturer: Yageo; Manufacturer Part Num: CC0603KRX7R8BB472; Num Pins: 2; Part Class: CAPACITORS; RATED_VOLTAGE: 25V; RoHS Compliant: RoHS Compliant; Tolerance: 10%
C807 C824 = CAP: CAPC,NP0,0402,330PF,50V,+/-10%; Item Num: K13738-001; Manufacturer: Murata; Manufacturer Part Num: GRM1555C1H331JA01D
C809 C826 = CAP: CAP CER 10UF 6.3V X5R 0402; Item Num: K46607-001; Lead Free Status: Lead Free; Manufacturer: Murata Electronics North America; Manufacturer Part Num: GRJ155R60J106ME11D; Num Pins: 2; PART_SUBCLASS: CAPACITORS; Part Class: CAPACITORS; RATED_VOLTAGE: 6.3V; RoHS Compliant: RoHS Compliant; Temperature Coefficient: X5R
C810 C812 C827 C829 = Cap,_NP,_1206: CAP - CERAMIC, 10UF, 10%, X5R, 16V, 0805; Dielectric: X5R; Item Num: K68729-001; Manufacturer: Yageo; Manufacturer Part Num: CC0805KKX5R7BB106; Part Number: CC0805KKX5R7BB106; TOLERANCE: ±10%; Voltage: 16V
C811 C813 C828 C830 = Cap,_NP,_1206: CAPC,X5R,0603,4.7UF,16.00V,+/- 10%; Agile Part Number: P03-15063R; Dielectric: X5R; Item Num: 602433-099; Manufacturer: Murata; Manufacturer Part Num: GRM188R61C475KAAJD; Part Number: GRM188R61C475KAAJD; TOLERANCE: ±10%; Voltage: 16V
C814 C831 = PCAP: CAPS,TA-P,D20,150.00uF,16.00V,+/- 20%,D20; Item Num: H97831-001; LIFECYCLE_PHASE: Active; Lead Free Status: Lead Free; MFR_LIFECYCLE: Active; Manufacturer: Panasonic; Manufacturer Part Num: 1CTQC15173F1; Num Pins: 2; PART_SUBCLASS: CAPACITORS; RATED_VOLTAGE: 16V; RoHS Compliant: RoHS Compliant; TOLERANCE: +/-20%
C818 C832 C834 = CAP: CAPC,X5R,1210,330.000UF,4.000V,+/- 20%; Dielectric: X5R; Item Num: 644066-175; Manufacturer: Murata; Manufacturer PN: GRM32ER60G337ME05L; Manufacturer Part Num: GRM32ER60G337ME05L; RATED_VOLTAGE: 4V; RoHS Compliant: Yes; Tolerance: 20%; Working Voltage: 4V
C820 = CAP: CAPC,X5R,1210,330.000UF,4.000V,+/- 20%; Dielectric: X5R; IPN: xxxxxx-xxx; Item Num: 644066-175; Manufacturer: Murata; Manufacturer PN: GRM32ER60G337ME05L; Manufacturer Part Num: GRM32ER60G337ME05L; RATED_VOLTAGE: 4V; RoHS Compliant: Yes; Tolerance: 20%; Working Voltage: 4V
L20 L21 = Inductor,_Discrete: FIXED INDUCTORS 0.82UH 8A,; Agile Part Number: 14293; Item Num: M16460-001; Manufacturer: Coil Craft; Package: 3740
R657 R669 = RESISTOR: RES,35.7K OHMS,1.0%,1/16W, 0402; AGILE_LINK: http://sj-agile9app/Agile/PLMServlet?action=OpenEmailObject&classid=10000&objid=146548997; Item Num: G21796-045; LIFECYCLE_PHASE: Active; Lead Free Status: No; MFR_LIFECYCLE: Active; Manufacturer: Yageo; Manufacturer Part Num: RC0402FR-0735K7P; Num Pins: 2; PART_SUBCLASS: RESISTORS; POWER: 1/16W; RoHS Compliant: Yes; TOLERANCE: 1%
R658 R670 R970 R978 = RESISTOR: RES,332K OHMS,1.0%,1/16W, 0402; AGILE_LINK: http://sj-agile9app/Agile/PLMServlet?action=OpenEmailObject&classid=10000&objid=146548997; Item Num: A93548-501; LIFECYCLE_PHASE: Active; Lead Free Status: No; MFR_LIFECYCLE: Active; Manufacturer: Yageo; Manufacturer Part Num: RC0402FR-07332KL; Num Pins: 2; PART_SUBCLASS: RESISTORS; POWER: 1/16W; RoHS Compliant: Yes; TOLERANCE: 1%
R659 R661 R674 R675 = RESISTOR: RES,14.0K OHMS,1.0%,1/16W, 0402; AGILE_LINK: http://sj-agile9app/Agile/PLMServlet?action=OpenEmailObject&classid=10000&objid=146548997; Item Num: A93548-206; LIFECYCLE_PHASE: Active; Lead Free Status: No; MFR_LIFECYCLE: Active; Manufacturer: Yageo; Manufacturer Part Num: RC0402FR-0714KL; Num Pins: 2; PART_SUBCLASS: RESISTORS; POWER: 1/16W; RoHS Compliant: Yes; TOLERANCE: 1%
R665 R666 R677 R678 = RESISTOR: RES D,0402,0.00 OHM,5.00%,1/16W; Altera Part No.: P02-14020R; Item Num: A93549-001; LIFECYCLE_PHASE: Active; Lead Free Status: No; MFR_LIFECYCLE: Active; Manufacturer: Panasonic; Manufacturer Part Num: ERJ-2GE0R00X; Num Pins: 2; PART_SUBCLASS: RESISTORS; POWER: 1/16W; Part Class: RESISTORS; RoHS Compliant: RoHS Compliant; Tolerance: +/-5%
C783 = CAP: CAP CER 47UF 10V X6S 1206; AGILE_LINK: http://sj-agile9app/Agile/PLMServlet?action=OpenEmailObject&classid=10000&objid=257560276; CAPACITANCE: 47uF; IPN: xxxxxx-xxx; Item Num: H65935-001; LIFECYCLE_PHASE: Active; Lead Free Status: Not Lead Free; MFR_LIFECYCLE: Active; Manufacturer: TDK; Manufacturer Part Num: C3216X6S1A476M160AC; Num Pins: 2; PART_SUBCLASS: CAPACITORS; RATED_VOLTAGE: 10V; RoHS Compliant: RoHS Compliant; TOLERANCE: 20%; TYPE: X6S
C784 = CAP: CAP,22u,X5R,10%,25V,1206; AGILE_LINK: http://sj-agile9app/Agile/PLMServlet?action=OpenEmailObject&classid=10000&objid=257560276; CAPACITANCE: 4.7uF; Item Num: 644066-121; LIFECYCLE_PHASE: Active; Lead Free Status: Not Lead Free; MFR_LIFECYCLE: Active; Manufacturer: Murata; Manufacturer Part Num: GRM31CR61E226KE15L; Num Pins: 2; PART_SUBCLASS: CAPACITORS; RATED_VOLTAGE: 25V; RoHS Compliant: RoHS Compliant; TOLERANCE: 10%; Thermal Coefficient: X6S
C785 C1360 C1361 C1381 C1382 = CAP: CAP,22u,X5R,10%,25V,1206; AGILE_LINK: http://sj-agile9app/Agile/PLMServlet?action=OpenEmailObject&classid=10000&objid=257560276; CAPACITANCE: 4.7uF; IPN: xxxxxx-xxx; Item Num: 644066-121; LIFECYCLE_PHASE: Active; Lead Free Status: Not Lead Free; MFR_LIFECYCLE: Active; Manufacturer: Murata; Manufacturer Part Num: GRM31CR61E226KE15L; Num Pins: 2; PART_SUBCLASS: CAPACITORS; RATED_VOLTAGE: 25V; RoHS Compliant: RoHS Compliant; TOLERANCE: 10%; Thermal Coefficient: X6S
C2004 = CAP: CAPC,X7R,0402,1.5NF,16.00V,+/- 10%; Dielectric: X6S; Item Num: A31095-023; LIFECYCLE_PHASE: Active; Lead Free Status: Lead Free; Manufacturer: TDK CORPORATION OF AMERICA; Manufacturer Part Num: C1005X7R1H152KTB09N; Num Pins: 2; Part Class: CAPACITORS; RATED_VOLTAGE: 16V; RoHS Compliant: RoHS Compliant; Tolerance: +/- 10%
C7525 = CAP: CAPC,X6S,0402,1.00UF,25.00V,+/- 10%; Item Num: H81594-001; Lead Free Status: Yes; Manufacturer: Murata; Manufacturer Part Num: GRM155C81E105KE11D; Num Pins: 2; Part Class: CAPACITORS; RATED_VOLTAGE: 25V; RoHS Compliant: Yes; Temperature Coefficient: X6S; Voltage: 25V
C7588 = T523H227M025APE070: CAP, TANT, 220 uF, 20%, 25V, 7361-20, SMD; Item Num: M76712-001; MANUFACTURER: KYOCERA; Manufacturer Part Num: TCN4227M025R0100; PART_NUMBER: TCN4227M025R0100; RATED_VOLTAGE: 25V
C7589-C7592 = CAP: CAP - CER, 22UF, 25V, 10%, X5R, 1206; Agile Part Number: P03-17640R; Item Num: K28232-001; Lead Free Status: Yes; Manufacturer: Murata; Manufacturer Part Num: GRM31CR61E226KE15L; Num Pins: 2; Part Class: Capacitors; Price: 0; RATED_VOLTAGE: 25V; RoHS Compliant: Yes
C7593-C7595 C7597-C7599 = CAP: CAP CER 100UF 6.3V X6T 1206; AGILE_LINK: http://sj-agile9app/Agile/PLMServlet?action=OpenEmailObject&classid=10000&objid=257560276; Item Num: H65271-004; LIFECYCLE_PHASE: Active; Lead Free Status: Lead Free; MFR_LIFECYCLE: Active; Manufacturer: Murata; Manufacturer Part Num: GRM31CD80J107ME39L; Num Pins: 2; PART_SUBCLASS: CAPACITORS; RATED_VOLTAGE: 6.3V; RoHS Compliant: RoHS Compliant; TOLERANCE: 20%; Temperature Coefficient: X6T
C7596 C7600 = PCAP: CAP TANT POLY 470UF 6.3V 2917; ESR: 10mOHM; Item Num: D96354-001; LIFECYCLE_PHASE: Active; Lead Free Status: Lead Free; MFR_LIFECYCLE: Active; Manufacturer: Panasonic; Manufacturer Part Num: 6TPF470MAH; Num Pins: 2; PART_SUBCLASS: CAPACITORS; RATED_VOLTAGE: 6.3V; RoHS Compliant: RoHS Compliant; Working Voltage: 6.3V
C7655 = CAP: CAP - CER, 1UF, 25V, 10%, X5R, 0402; Item Num: H29050-001; Lead Free Status: Yes; Manufacturer: TDK Electronics; Manufacturer Part Num: CGB2A1X5R1E105K033BC; Num Pins: 2; Part Class: CAPACITORS; RATED_VOLTAGE: 25V; RoHS Compliant: Yes
C7663 = CAP: CAP,CER,360PF,50V,1%,C0G,0402,; AGILE_LINK: http://sj-agile9app/Agile/PLMServlet?action=OpenEmailObject&classid=10000&objid=215384813; CAPACITANCE: 1000pF; Item Num: M78145-001; LIFECYCLE_PHASE: Active; Lead Free Status: Lead Free; MFR_LIFECYCLE: Active; Manufacturer: KEMET; Manufacturer Part Num: C0402C361F5JAC7867; Num Pins: 2; PACKAGING: Tape & Reel (TR); PART_SUBCLASS: CAPACITORS; RATED_VOLTAGE: 50V; RoHS Compliant: RoHS Compliant; Supplier Part Num: C0402C361F5JAC7867; Tolerance: +/-1%
D17 = PMEG2005AEL,315: Item Num: H64664-001; Manufacturer Part Num: PMEG2005AEL
FB26 = INDUCTOR: FERRITE BEAD 800MA 120 OHM; IPN: xxxxxx-xxx; Item Num: D92183-020; Lead Free Status: No; Manufacturer: Steward; Mfr Code: STED; Num Pins: 2; Part Class: Inductors; Price: 0.11; RoHS Compliant: Yes
R5835 = RESISTOR: RES D,0402,0.00 OHM,5.00%,1/16W; Altera Part No.: P02-14020R; Item Num: A93549-001; Lead Free Status: No; Manufacturer: Panasonic; Manufacturer Part Num: ERJ-2GE0R00X; Num Pins: 2; Part Class: RESISTORS; RoHS Compliant: Yes; Tolerance: +/-5%
R5836 = RESISTOR: RES D,0402,0.00 OHM,5.00%,1/16W; Altera Part No.: P02-14020R; Item Num: A93549-001; Lead Free Status: No; Manufacturer: YAGEO CORP.; Manufacturer Part Num: RC0402JR-070RL; Num Pins: 2; Part Class: RESISTORS; Price: 0; RoHS Compliant: Yes; Tolerance: 5%
R5837 R5847 R5850 R6054 = RESISTOR: RES D,0402,0.00 OHM,5.00%,1/16W; Altera Part No.: P02-14020R; Item Num: A93549-001; Lead Free Status: No; Manufacturer: YAGEO CORP.; Manufacturer Part Num: RC0402JR-070RL; Num Pins: 2; Part Class: RESISTORS; RoHS Compliant: Yes; Tolerance: ± 5%
R5838 = RESISTOR: RES D,0402,0.00 OHM,5.00%,1/16W; Altera Part No.: P02-14020R; Item Num: A93549-001; Lead Free Status: No; Manufacturer: YAGEO CORP.; Manufacturer Part Num: RC0402JR-070RL; Num Pins: 2; Part Class: RESISTORS; Price: 0; RoHS Compliant: Yes; Tolerance: +/-5%
R5839 R5842 R5848 R6146 = RESISTOR: RES,10.0K OHMS,1.0%,1/16W, 0402; AGILE_LINK: http://sj-agile9app/Agile/PLMServlet?action=OpenEmailObject&classid=10000&objid=146548997; Item Num: K28115-001; LIFECYCLE_PHASE: Active; Lead Free Status: No; MFR_LIFECYCLE: Active; Manufacturer: Panasonic; Manufacturer Part Num: ERJ-2RKF1002X; Num Pins: 2; PART_SUBCLASS: RESISTORS; POWER: 1/16W; RoHS Compliant: Yes; TOLERANCE: ± 1%
R5840 = RESISTOR: RES,10.0K OHMS,1.0%,1/16W, 0402; AGILE_LINK: http://sj-agile9app/Agile/PLMServlet?action=OpenEmailObject&classid=10000&objid=146548997; Item Num: A93548-034; LIFECYCLE_PHASE: Active; Lead Free Status: No; MFR_LIFECYCLE: Active; Manufacturer: Panasonic; Manufacturer Part Num: ERJ-2RKF1002X; Num Pins: 2; PART_SUBCLASS: RESISTORS; POWER: 1/16W; RoHS Compliant: Yes; TOLERANCE: ± 1%
R5841 R5845 = RESISTOR: RES,10.0K OHMS,1.0%,1/16W, 0402; AGILE_LINK: http://sj-agile9app/Agile/PLMServlet?action=OpenEmailObject&classid=10000&objid=146548997; Item Num: A93548-034; LIFECYCLE_PHASE: Active; Lead Free Status: No; MFR_LIFECYCLE: Active; Manufacturer: Panasonic; Manufacturer Part Num: ERJ-2RKF1002X; Num Pins: 2; PART_SUBCLASS: RESISTORS; POWER: 1/16W; RESISTANCE: 10.0K; RoHS Compliant: Yes; TOLERANCE: ± 1%
R5849 R5854 = RESISTOR: RES D,0402,0.00 OHM,5.00%,1/16W; Altera Part No.: P02-14020R; Item Num: A93549-001; Lead Free Status: No; Manufacturer: YAGEO CORP.; Manufacturer Part Num: RC0402JR-070RL; Num Pins: 2; Part Class: RESISTORS; Price: 0; RoHS Compliant: Yes; Tolerance: ± 5%
R5853 = Resistor,_0402: RES_D,0402,1.62kOHM,1/16W,N/A; Item Num: K96980-001; Manufacturer: YAGEO CORP.; Manufacturer Part Num: RT0402BRD071K62L; Package: 0402; Part Number: RT0402BRD071K62L; TOLERANCE: ±0.1%
R5923 = Resistor,_0402: RES_D,0402,4.22kOHM,1.00%,1/16W; Item Num: G21796-065; Manufacturer: Vishay; Manufacturer Part Num: WR04X4221FTR; Part Number: WR04X4221FTR; Tolerance (%): ± 1%
R5924 = Resistor,_0402: RES_D,0402,15.4kOHM,1.00%,1/16W; Item Num: G21796-108; Manufacture: YAGEO CORP.; Manufacturer: WALSIN TECHNOLOGY CORP; Manufacturer Part Num: RC0402FR-0715K4P; Part Number: RC0402FR-0715K4P; Power: 1/16W; TOLERANCE: ± 1%; Tolerance (%): ± 1%
R6148 = RESISTOR: RES,4.70K OHMS,1.0%,1/16W,0402; Item Num: A93548-517; Lead Free Status: No; Manufacturer: Vishay; Manufacturer Part Num: CRCW04024K70FKED; Manufacturer's Part No.: ERJ-2GEJ472X; Num Pins: 2; Part Class: RESISTORS; Price: 0; RoHS Compliant: Yes; Tolerance (%): ± 1%
R6156 = Resistor,_0402: RES 20.0K ohm, 1/16W 1% 0402 SMD; Agile Part Number: P02-15647R; Item Num: A93548-181; Manufacturer: Yageo; Manufacturer Part Num: RC0402FR-0720KL; Power: 1/16W; TOLERANCE: ±1%
R6159 R6201 = RESISTOR: RES D,0402,0.00 OHM,5.00%,1/16W; Altera Part No.: P02-14020R; Item Num: A93549-001; Lead Free Status: No; Manufacturer: Panasonic; Manufacturer Part Num: ERJ-2GE0R00X; Num Pins: 2; Part Class: RESISTORS; RoHS Compliant: Yes; Tolerance: ± 5%
TP1000 = TESTPOINT
U118 = LTM4686EV-1#PBF: Item Num: M75350-001
C1345 C1366 = CAP: CAP CER 0.1UF 25V 20% X7R 0402; Dielectric: X7R; IPN: xxxxxx-xxx; Item Num: A36096-112; LIFECYCLE_PHASE: Active; Lead Free Status: Lead Free; Manufacturer: Murata; Manufacturer Part Num: GRM155R71E104KE14D; Num Pins: 2; Part Class: CAPACITORS; RATED_VOLTAGE: 25V; RoHS Compliant: RoHS Compliant; Tolerance: 10%
C1346 C1350 = CAP: CAPACITANCE: 0.1uF; Dielectric: X6S; Item Num: H90637-001; LIFECYCLE_PHASE: Active; Lead Free Status: Lead Free; Manufacturer: Murata; Manufacturer Part Num: GRM155R71E104KE14D; Num Pins: 2; Part Class: CAPACITORS; RATED_VOLTAGE: 10V; RoHS Compliant: RoHS Compliant; Tolerance: 10%
C1347 C1348 C1368 C1369 = CAP: CAP, CERAMIC, 27PF, 1%, NPO, 50V, 0402; AGILE_LINK: http://sj-agile9app/Agile/PLMServlet?action=OpenEmailObject&classid=10000&objid=213459014; Item Num: K13702-001; Lead Free Status: Lead Free; MFR_LIFECYCLE: Active; Manufacturer: Murata; Manufacturer Part Num: GRM1555C1H270FA01D; Num Pins: 2; PART_SUBCLASS: CAPACITORS; RoHS Compliant: Yes
C1351 C1354 C1372 C1375 C1386 C1387 = CAP: CAP CER 100UF 6.3V X6T 1206; AGILE_LINK: http://sj-agile9app/Agile/PLMServlet?action=OpenEmailObject&classid=10000&objid=257560276; IPN: xxxxxx-xxx; Item Num: H65271-004; LIFECYCLE_PHASE: Active; Lead Free Status: Not Lead Free; MFR_LIFECYCLE: Active; Manufacturer: Murata; Manufacturer PN: GRM31CR60J107ME39L; Manufacturer Part Num: GRM31CR60J107ME39L; Num Pins: 2; PART_SUBCLASS: CAPACITORS; RATED_VOLTAGE: 6.3V; RoHS Compliant: RoHS Compliant; TOLERANCE: 20%; Temperature Coefficient: X6T; Working Voltage: 6.3V
C1355 C1376 = CAP: CAP CER 100UF 6.3V X6T 1206; AGILE_LINK: http://sj-agile9app/Agile/PLMServlet?action=OpenEmailObject&classid=10000&objid=257560276; CAPACITANCE: 100uF; IPN: xxxxxx-xxx; Item Num: H65271-004; LIFECYCLE_PHASE: Active; Lead Free Status: Not Lead Free; MFR_LIFECYCLE: Active; Manufacturer: Murata; Manufacturer PN: GRM31CR60J107ME39L; Manufacturer Part Num: GRM31CR60J107ME39L; Num Pins: 2; PART_SUBCLASS: CAPACITORS; RATED_VOLTAGE: 6.3V; RoHS Compliant: RoHS Compliant; TOLERANCE: 20%; Temperature Coefficient: X6T; Working Voltage: 6.3V
C1356 C1388 = Cap,_NP,_0402: CAP, CERAMIC, 100pF, 0402, 5%, 50VDC, NPO; Item Num: K13768-001; Manufacturer: Murata; Manufacturer Part Num: GRM1555C1H101JA01D
C1364 C1385 = CAP: CAPC,X6S,0402,1.00UF,25.00V,+/- 10%; IPN: xxxxxx-xxx; Item Num: H81594-001; Lead Free Status: Yes; Manufacturer: Murata; Manufacturer Part Num: GRM155C81E105KE11D; Num Pins: 2; Part Class: CAPACITORS; RATED_VOLTAGE: 25V; RoHS Compliant: Yes; Temperature Coefficient: X6S; Voltage: 25V
C1367 C1371 = CAP: CAP CER 2.2UF 10V X6S 0402; CAPACITANCE: 0.1uF; Dielectric: X6S; Item Num: H90637-001; LIFECYCLE_PHASE: Active; Lead Free Status: Lead Free; Manufacturer: Murata; Manufacturer Part Num: GRM155C81A225KE44D; Num Pins: 2; Part Class: CAPACITORS; RATED_VOLTAGE: 10V; RoHS Compliant: RoHS Compliant; Tolerance: 10%
R955 R956 R965 R966 = RESISTOR: RES, 100K OHMS, 1.0%, 1/16W, 0402; AGILE_LINK: http://sj-agile9app/Agile/PLMServlet?action=OpenEmailObject&classid=10000&objid=146932246; Item Num: E86804-001; LIFECYCLE_PHASE: Active; MFR_LIFECYCLE: Active; Manufacturer: Panasonic; Manufacturer Part Num: ERJ-2RKF1003X; Num Pins: 2; PART_SUBCLASS: RESISTORS; POWER: 1/10W; RoHS Compliant: RoHS Compliant; TOLERANCE: +/-1%
R957 R959 R960 R967 R971 R972 R980 R981 = RESISTOR: RES, 100K OHMS, 1.0%, 1/16W, 0402; AGILE_LINK: http://sj-agile9app/Agile/PLMServlet?action=OpenEmailObject&classid=10000&objid=146932246; Item Num: E86804-001; LIFECYCLE_PHASE: Active; MFR_LIFECYCLE: Active; Manufacturer: Panasonic; Manufacturer Part Num: ERJ-2RKF1003X; Num Pins: 2; PART_SUBCLASS: RESISTORS; POWER: 1/10W; RESISTANCE: 100K; RoHS Compliant: RoHS Compliant; TOLERANCE: +/-1%
R958 R969 = RESISTOR: RES D,0402,0.00 OHM,5.00%,1/16W; Agile IPN: P02-14020R; Altera Part No.: P02-14020R; Item Num: A93549-001; Lead Free Status: No; Manufacturer: Panasonic; Manufacturer Part Num: ERJ-2GE0R00X; Num Pins: 2; Part Class: RESISTORS; RoHS Compliant: Yes; Tolerance: 5%
R961 R963 R973 R975 = RESISTOR: RES, 10 OHM, 1%, 1/16W, 0402; AGILE_LINK: http://sj-agile9app/Agile/PLMServlet?action=OpenEmailObject&classid=10000&objid=146932246; Item Num: A93548-031; LIFECYCLE_PHASE: Active; MFR_LIFECYCLE: Active; Manufacturer: Panasonic; Manufacturer Part Num: ERJ-2RKF10R0X; Num Pins: 2; PART_SUBCLASS: RESISTORS; POWER: 1/16W; RoHS Compliant: RoHS Compliant; TOLERANCE: +/-1%
R964 R976 = RES: RES 75K OHM 1% 1/16W 0402 SMD; Item Num: A93548-325; Manufacturer: Panasonic; Manufacturer Part Num: ERJ-2RKF7502X; Package: SMD; Part Class: RESISTORS; Type: Resistor
R977 R979 = RESISTOR: RES,4.70K OHMS,1.0%,1/16W,0402; IPN: xxxxxx-xxx; Item Num: A93548-517; Lead Free Status: No; Manufacturer: Vishay; Manufacturer Part Num: CRCW04024K70FKED; Manufacturer's Part No.: ERJ-2GEJ472X; Num Pins: 2; Part Class: RESISTORS; Price: 0; RoHS Compliant: Yes
TP19-TP22 = PAD_STYLE_C: TESTPOINT, PCB COPPER FEATURE; CLASS: IO; FPLIST: PADSTYLE1,PADSTYLE2,PADSTYLE3,PADSTYLE4,PADSTYLE5,PADSTYLE6,PADSTYLE7,PADSTYLE8; Manufacturer: N/A; Manufacturer PN: N/A; PART_FIELD_01: SW; PART_NUMBER: PCBPADS-1
U66 U67 = LTM4657-BGA_0: IC,Step-Down uModule Reg,BGA-49; CLASS: IC; Inventory Qty: 0; Item Num: M29833-001; Manufacturer: ANALOG DEVICES; Manufacturer PN: LTM4657EY#PBF; Manufacturer Part Num: LTM4657EY#PBF; PART_NUMBER: LTM4657EY#PBF; Package Type: BGA-49

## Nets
5V: C7525.1 R5837.2 R6054.1 ; also on sheet 48 57 65 68 73
12V_G2: C810.2 C811.2 C812.2 C813.2 C814.1 C827.2 C828.2 C829.2 C830.2 C831.1 C1360.1 C1361.1 C1364.2 C1381.1 C1382.1 C1385.2 C7588.1 C7589.2 C7590.2 C7591.2 C7592.2 C7655.2 C7767.2 C7768.2 C7769.2 C7770.2 C7783.1 R663.2 R673.2 R956.2 R966.2 R5838.1 R6268.2 U66.D3(VIN) U66.D4(VIN) U66.E3(VIN) U66.E4(VIN) U66.F4(VIN) U66.G4(VIN) U67.D3(VIN) U67.D4(VIN) U67.E3(VIN) U67.E4(VIN) U67.F4(VIN) U67.G4(VIN) U68.4(PVIN) U68.5(PVIN) U68.18(PVIN) U68.19(PVIN) U69.4(PVIN) U69.5(PVIN) U69.18(PVIN) U69.19(PVIN) U118.A9(VIN0_1) U118.B9(VIN0_2) U118.C9(VIN0_3) U118.D9(VIN0_4) U118.J9(VIN1_1) U118.K9(VIN1_2) U118.L9(VIN1_3) U118.M9(VIN1_4) U137.4(PVIN) U137.5(PVIN) U137.18(PVIN) U137.19(PVIN) ; also on sheet 53 57 63 64 65 66 67 69 70 71 73
GND: C783.1 C784.2 C785.2 C808.2 C809.2 C810.1 C811.1 C812.1 C813.1 C814.2 C815.2 C816.2 C817.2 C818.1 C819.2 C820.1 C825.2 C826.2 C827.1 C828.1 C829.1 C830.1 C831.2 C832.1 C833.2 C834.1 C835.2 C837.2 C838.2 C1346.2 C1350.2 C1351.1 C1354.1 C1355.1 C1360.2 C1361.2 C1364.1 C1367.2 C1371.2 C1372.1 C1375.1 C1376.1 C1381.2 C1382.2 C1385.1 C1386.1 C1387.1 C7525.2 C7588.2 C7589.1 C7590.1 C7591.1 C7592.1 C7593.1 C7594.1 C7595.1 C7596.2 C7597.1 C7598.1 C7599.1 C7600.2 C7655.1 C7765.2 C7766.2 C7767.1 C7768.1 C7769.1 C7770.1 C7771.2 C7772.2 C7773.2 C7774.2 C7775.2 C7776.2 C7783.2 R662.1 R665.1 R667.1 R672.1 R677.1 R679.1 R960.1 R963.1 R972.1 R975.1 R977.1 R979.1 R980.2 R981.2 R6148.1 R6201.1 R6267.1 R6270.1 R6272.1 ST3.2 ST6.2 ST9.1 ST10.1 ST31.1 ST32.1 U66.B2(GND) U66.B6(GND) U66.C3(GND) U66.C4(GND) U66.C5(GND) U66.C6(GND) U66.C7(GND) U66.D5(GND) U66.D6(GND) U66.D7(GND) U66.E5(GND) U66.E6(GND) U66.E7(GND) U66.F5(GND) U66.F6(GND) U66.F7(GND) U66.G6(GND) U66.G7(GND) U67.B2(GND) U67.B6(GND) U67.C3(GND) U67.C4(GND) U67.C5(GND) U67.C6(GND) U67.C7(GND) U67.D5(GND) U67.D6(GND) U67.D7(GND) U67.E5(GND) U67.E6(GND) U67.E7(GND) U67.F5(GND) U67.F6(GND) U67.F7(GND) U67.G6(GND) U67.G7(GND) U68.6(GND) U68.7(GND) U68.8(GND) U68.15(GND) U68.16(GND) U68.17(GND) U68.29(GND) U68.30(GND) U68.31(GND) U68.32(GND) U69.6(GND) U69.7(GND) U69.8(GND) U69.15(GND) U69.16(GND) U69.17(GND) U69.29(GND) U69.30(GND) U69.31(GND) U69.32(GND) U118.A2(GND) U118.A3(GND) U118.A4(GND) U118.A5(GND) U118.A6(GND) U118.A7(GND) U118.A8(GND) U118.B2(GND) U118.B3(GND) U118.B4(GND) U118.B5(GND) U118.B6(GND) U118.B7(GND) U118.C2(GND) U118.C4(GND) U118.C5(GND) U118.C6(GND) U118.C7(GND) U118.C8(GND) U118.D2(GND) U118.D5(GND) U118.E1(GND) U118.E9(GND) U118.F1(GND) U118.F8(GND) U118.G1(GND) U118.G8(GND) U118.G9(GND) U118.H1(GND) U118.H8(GND) U118.H9(GND) U118.J2(GND) U118.J8(GND) U118.K2(GND) U118.K5(GND) U118.K6(GND) U118.K7(GND) U118.K8(GND) U118.L2(GND) U118.L3(GND) U118.L4(GND) U118.L5(GND) U118.L6(GND) U118.L7(GND) U118.M2(GND) U118.M3(GND) U118.M4(GND) U118.M5(GND) U118.M6(GND) U118.M7(GND) U118.M8(GND) U137.6(GND) U137.7(GND) U137.8(GND) U137.15(GND) U137.16(GND) U137.17(GND) U137.29(GND) U137.30(GND) U137.31(GND) U137.32(GND) ; also on sheet 9 10 11 13 14 15 16 17 18 19 20 21 22 23 25 26 27 28 29 30 31 32 33 34 35 36 38 39 40 41 42 43 44 45 46 47 48 49 50 51 52 53 54 55 56 57 63 64 65 66 67 68 69 70 71 72 73 74 75 76 77
SVIN4: C808.1 R663.1 U68.3(SVIN)
SVIN5: C825.1 R673.1 U69.3(SVIN)
VCCA_PLL_FLTR: C783.2 C784.1 C785.1 FB26.1 ; also on sheet 39 75
VCCED_AGND: C1345.2 C1347.2 C1348.2 R978.2 ST31.2 U66.A7(TSENSE-)
VCCED_GXR_EN: R979.2 U66.B4(RUN) ; also on sheet 51
VCCED_GXR_PG: R955.2 U66.B5(PGOOD) ; also on sheet 49
VCCED_SNS_N: R963.2 R964.1 U66.C2(VOUTS-)
VCCED_SNS_P: R961.1 U66.B1(VOUTS+)
VCCERT_FGT_GXF_EN: R660.1 R662.2 U68.2(RUN) ; also on sheet 51
VCCERT_FGT_GXF_PG: R656.1 U68.26(PGOOD) ; also on sheet 50
VCCL_HPS_AGND: C1366.2 C1368.2 C1369.2 R970.2 ST32.2 U67.A7(TSENSE-)
VCCL_HPS_EN: R977.2 U67.B4(RUN) ; also on sheet 51
VCCL_HPS_PG: R965.2 U67.B5(PGOOD) ; also on sheet 50
VCCL_HPS_SNS_N: R975.2 R976.1 U67.C2(VOUTS-)
VCCL_HPS_SNS_P: R973.1 U67.B1(VOUTS+)
VCCR_CORE: C7593.2 C7594.2 C7595.2 C7596.1 C7597.2 C7598.2 C7599.2 C7600.1 FB26.2 R5835.1 TP972.1 U118.A1(VOUT0_1) U118.B1(VOUT0_2) U118.C1(VOUT0_3) U118.D1(VOUT0_4) U118.J1(VOUT1_1) U118.K1(VOUT1_2) U118.L1(VOUT1_3) U118.M1(VOUT1_4) ; also on sheet 39 75
VCCR_CORE_AGND: C7663.1 R5848.1 R5853.1 R5854.1 R5923.1 R5924.2 R6156.1 ST6.1 U118.F5(SGND) U118.F6(SGND) U118.G5(SGND) U118.G6(SGND)
VCCR_CORE_EN: R5850.2 ; also on sheet 51
VCCR_CORE_PG: D17.1(K) ; also on sheet 50
VCCRT_GXR_EN: R671.1 R672.2 U69.2(RUN) ; also on sheet 51
VCCRT_GXR_PG: R668.1 U69.26(PGOOD) ; also on sheet 50
VDD33_OUT1: C7766.1 R6261.2 R6265.2 R6269.2 U137.20(INTVCC)
0p9V_VCCED_GXR: C1350.1 C1351.2 C1354.2 C1355.2 C1356.1 C1386.2 R961.2 TP973.1 U66.A1(VOUT) U66.A2(VOUT) U66.A3(VOUT) U66.A4(VOUT) U66.A5(VOUT) U66.F3(VOUT1) U66.G1(VOUT1) U66.G2(VOUT1) U66.G3(VOUT1) ; also on sheet 38 75
0p9V_VCCL_HPS: C1371.1 C1372.2 C1375.2 C1376.2 C1387.2 C1388.1 R973.2 TP974.1 U67.A1(VOUT) U67.A2(VOUT) U67.A3(VOUT) U67.A4(VOUT) U67.A5(VOUT) U67.F3(VOUT1) U67.G1(VOUT1) U67.G2(VOUT1) U67.G3(VOUT1) ; also on sheet 38 75
1p0V_VCCERT_FGT_GXF: C815.1 C816.1 C817.1 C818.2 C819.1 C820.2 L20.2 R666.1 TP975.1 ; also on sheet 38 75
1p0V_VCCRT_GXR: C832.2 C833.1 C834.2 C835.1 C837.1 C838.1 L21.2 R678.1 TP976.1 ; also on sheet 38 75 77
3p3V: C7771.1 C7772.1 C7773.1 C7774.1 C7775.1 C7776.1 L30.2 R5839.2 R5840.2 R5841.2 R5842.2 R5845.2 R6146.2 R6271.1 TP971.1 ; also on sheet 54 63 65 66 67 69 70 71 72 73 74
3p3V_AGND: C7761.2 C7780.2 C7781.2 R6263.2 ST3.1
3p3V_EN: R6265.1 R6267.2 U137.2(RUN) ; also on sheet 49
3p3V_PG: R6261.1 U137.26(PGOOD) ; also on sheet 50
COMP_1p2: C2004.2 C7663.2 R5836.1 R6159.1 U118.H6(COMP1A)
FGT_AGND: C804.2 C805.1 C806.2 R658.2 ST9.2
GXR_AGND: C821.2 C822.1 C823.2 R670.2 ST10.2
INTVCC4: C809.1 R656.2 R660.2 R664.2 U68.20(INTVCC)
INTVCC5: C826.1 R668.2 R671.2 R676.2 U69.20(INTVCC)
LTM_PMBUS_ALERTn: R5847.2 ; also on sheet 63 65
LTM_SCL: U118.E4(SCL) ; also on sheet 63 65
LTM_SDA: U118.D4(SDA) ; also on sheet 63 65
PHMD4: R664.1 R667.2 U68.28(PHMODE)
PHMD5: R676.1 R679.2 U69.28(PHMODE)
PHMD137: R6269.1 R6272.2 U137.28(PHMODE)
VOSNS0_VCCR: R5835.2 U118.D7(VOSNS0+) U118.H7(VOSNS1)
N40710074: C821.1 U69.25(TRACK/SS)
N40710102: C822.2 R669.2 U69.24(ITH)
N40710172: R670.1 U69.27(RT)
N40710190: C824.1 R674.2 R675.2 U69.23(FB)
N40710194: C824.2 R674.1 R678.2
N40710315: R675.1 R677.2 U69.22(VOUTM)
N40710340: TP15.1 U69.1(CLKOUT)
N40710582: L21.1 U69.9(SW1) U69.10(SW2) U69.11(SW3) U69.12(SW4) U69.13(SW5) U69.14(SW6)
N41064371: C804.1 U68.25(TRACK/SS)
N41064404: C805.2 R657.2 U68.24(ITH)
N41064465: R658.1 U68.27(RT)
N41064483: C807.1 R659.2 R661.2 U68.23(FB)
N41064487: C807.2 R659.1 R666.2
N41064609: R661.1 R665.2 U68.22(VOUTM)
N41064634: TP14.1 U68.1(CLKOUT)
N41064896: L20.1 U68.9(SW1) U68.10(SW2) U68.11(SW3) U68.12(SW4) U68.13(SW5) U68.14(SW6)
N45054348: C1345.1 U66.E2(TRACK/SS)
N45054411: C1346.1 R955.1 R957.2 U66.B3(INTVCC)
N45054431: TP20.1 U66.F2(CLKOUT)
N45054433: TP19.1 U66.B7(SW)
N45054462: R956.1 U66.A6(TSENSE+)
N45054466: C1347.1 R958.2 R959.2 U66.D1(COMPa)
N45054537: R957.1 R960.2 U66.G5(PHMODE)
N45054575: R978.1 U66.E1(FREQ)
N45054598: R958.1 U66.F1(COMPb)
N45054604: C1348.1 R959.1
N45054651: R980.1 U66.D2(MODE/CLKIN)
N45054838: C1356.2 R964.2 U66.C1(FB)
N45056577: C1366.1 U67.E2(TRACK/SS)
N45056642: C1367.1 R965.1 R967.2 U67.B3(INTVCC)
N45056662: TP21.1 U67.F2(CLKOUT)
N45056664: TP22.1 U67.B7(SW)
N45056693: R966.1 U67.A6(TSENSE+)
N45056697: C1368.1 R969.2 R971.2 U67.D1(COMPa)
N45056768: R967.1 R972.2 U67.G5(PHMODE)
N45056806: R970.1 U67.E1(FREQ)
N45056829: R969.1 U67.F1(COMPb)
N45056835: C1369.1 R971.1
N45056882: R981.1 U67.D2(MODE/CLKIN)
N45057066: C1388.2 R976.2 U67.C1(FB)
N47824485: U118.J3(TSNS1A) U118.K3(TSNS1B)
N47824624: R5836.2 U118.J6(COMP1B)
N47824941: R5837.1 U118.F7(INTVCC1) U118.G7(INTVCC2)
N47824971: R5838.2 R6054.2 U118.F9(SVIN)
N47825075: R5839.1 U118.E5(SYNC)
N47825077: R5840.1 U118.H5(SHARE_CLK)
N47825108: R5845.1 R5847.1 U118.E3(~{ALERT})
N47825137: D17.2(A) R6146.1 U118.E2(~{GPIO0})
N47825141: U118.C3(TSNS0_1) U118.D3(TSNS0_2)
N47825168: R5848.2 U118.K4(WP)
N47825183: R5841.1 R5850.1 R6148.2 U118.F3(RUN0) U118.F4(RUN1)
N47825220: TP1006.1 U118.J4(VDD25)
N47825281: R5923.2 U118.G2(ASEL)
N47825319: R5924.1 U118.H2(FSWPHCFG)
N47825365: R5853.2 U118.G3(VOUT0CFG) U118.G4(VOUT1CFG)
N47825375: R5854.2 U118.H3(VTRIM0CFG) U118.H4(VTRIM1CFG)
N48009189: C823.1 R669.1
N48253770: TP1000.1(TP) U118.J5(VDD33)
N48809318: R5842.1 U118.F2(~{GPIO1})
N48818747: C2004.1 R6156.2
N48820208: R5849.2 U118.D6(COMP0B)
N48820211: R5849.1 R6159.2 U118.E6(COMP0A)
N49539229: R6201.2 U118.E7(VOSNS0-)
N50006329: C7761.1 U137.25(TRACK/SS)
N50006362: C7781.1 R6262.1 U137.24(ITH)
N50006438: R6263.1 U137.27(RT)
N50006442: C7764.1 R6264.2 R6266.2 U137.23(FB)
N50006446: C7764.2 R6266.1 R6271.2
N50006595: TP1005.1 U137.1(CLKOUT)
N50006597: R6270.2 R6288.1 U137.22(VOUTM)
N50006631: C7765.1 R6268.1 U137.3(SVIN)
N50006855: L30.1 U137.9(SW1) U137.10(SW2) U137.11(SW3) U137.12(SW4) U137.13(SW5) U137.14(SW6)
N50532265: C7780.1 R6262.2
N50568598: C806.1 R657.1
N51025331: R6264.1 R6288.2

Not connected (* = marked no-connect by the designer): U68 21(M/S)*; U69 21(M/S)*; U118 B8(SW0)* D8(VORB0+)* E8(VORB0-)* J7(VORB1)* L8(SW1)*; U137 21(M/S)*

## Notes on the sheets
sheet 58
- MAIN 12V to 3.3V
- Fswitch:
  1.5MHz
- AGND
- PGND
sheet 59
- PWR - VCCR_CORE,  VCCA_PLL
- 1V2 @ 20A
- VIN  : 4.5V to 17V
- VOUT : 1V2
- Tj   : -40 C TO 125 C
- ILOAD : 20A
- (Top Side 30mil pad,
  No Via)
- I2C ADDR : 45h
- FSW  : 575KHz
- NOTE: U118  Default configured for LTM4686EV-1 uModule
  If Changing to LTM4686EV
  Unmount R6054,R5837. Mount R5838
- AGND
- PGND
- 1.2V
- Place filter close to FPGA
sheet 60
- PWR - VCCED_GXR, VCCL_HPS
- Connect VCCED_SNS+ at remote location
- 0.9V
- R964 adjusted for 0.9V
- Connect VCCED_SNS- at remote location
- Connect VCCL_HPS_SNS+ at remote location
- 0.9V
- Connect VCCL_HPS_SNS- at remote location
sheet 61
- PWR - VCCERT_FGT_GXF
- Fswitch:
  500KHz
- 1.0V
sheet 62
- PWR - VCCRT_GXR
- Fswitch:
  500KHz
- 1.0V
